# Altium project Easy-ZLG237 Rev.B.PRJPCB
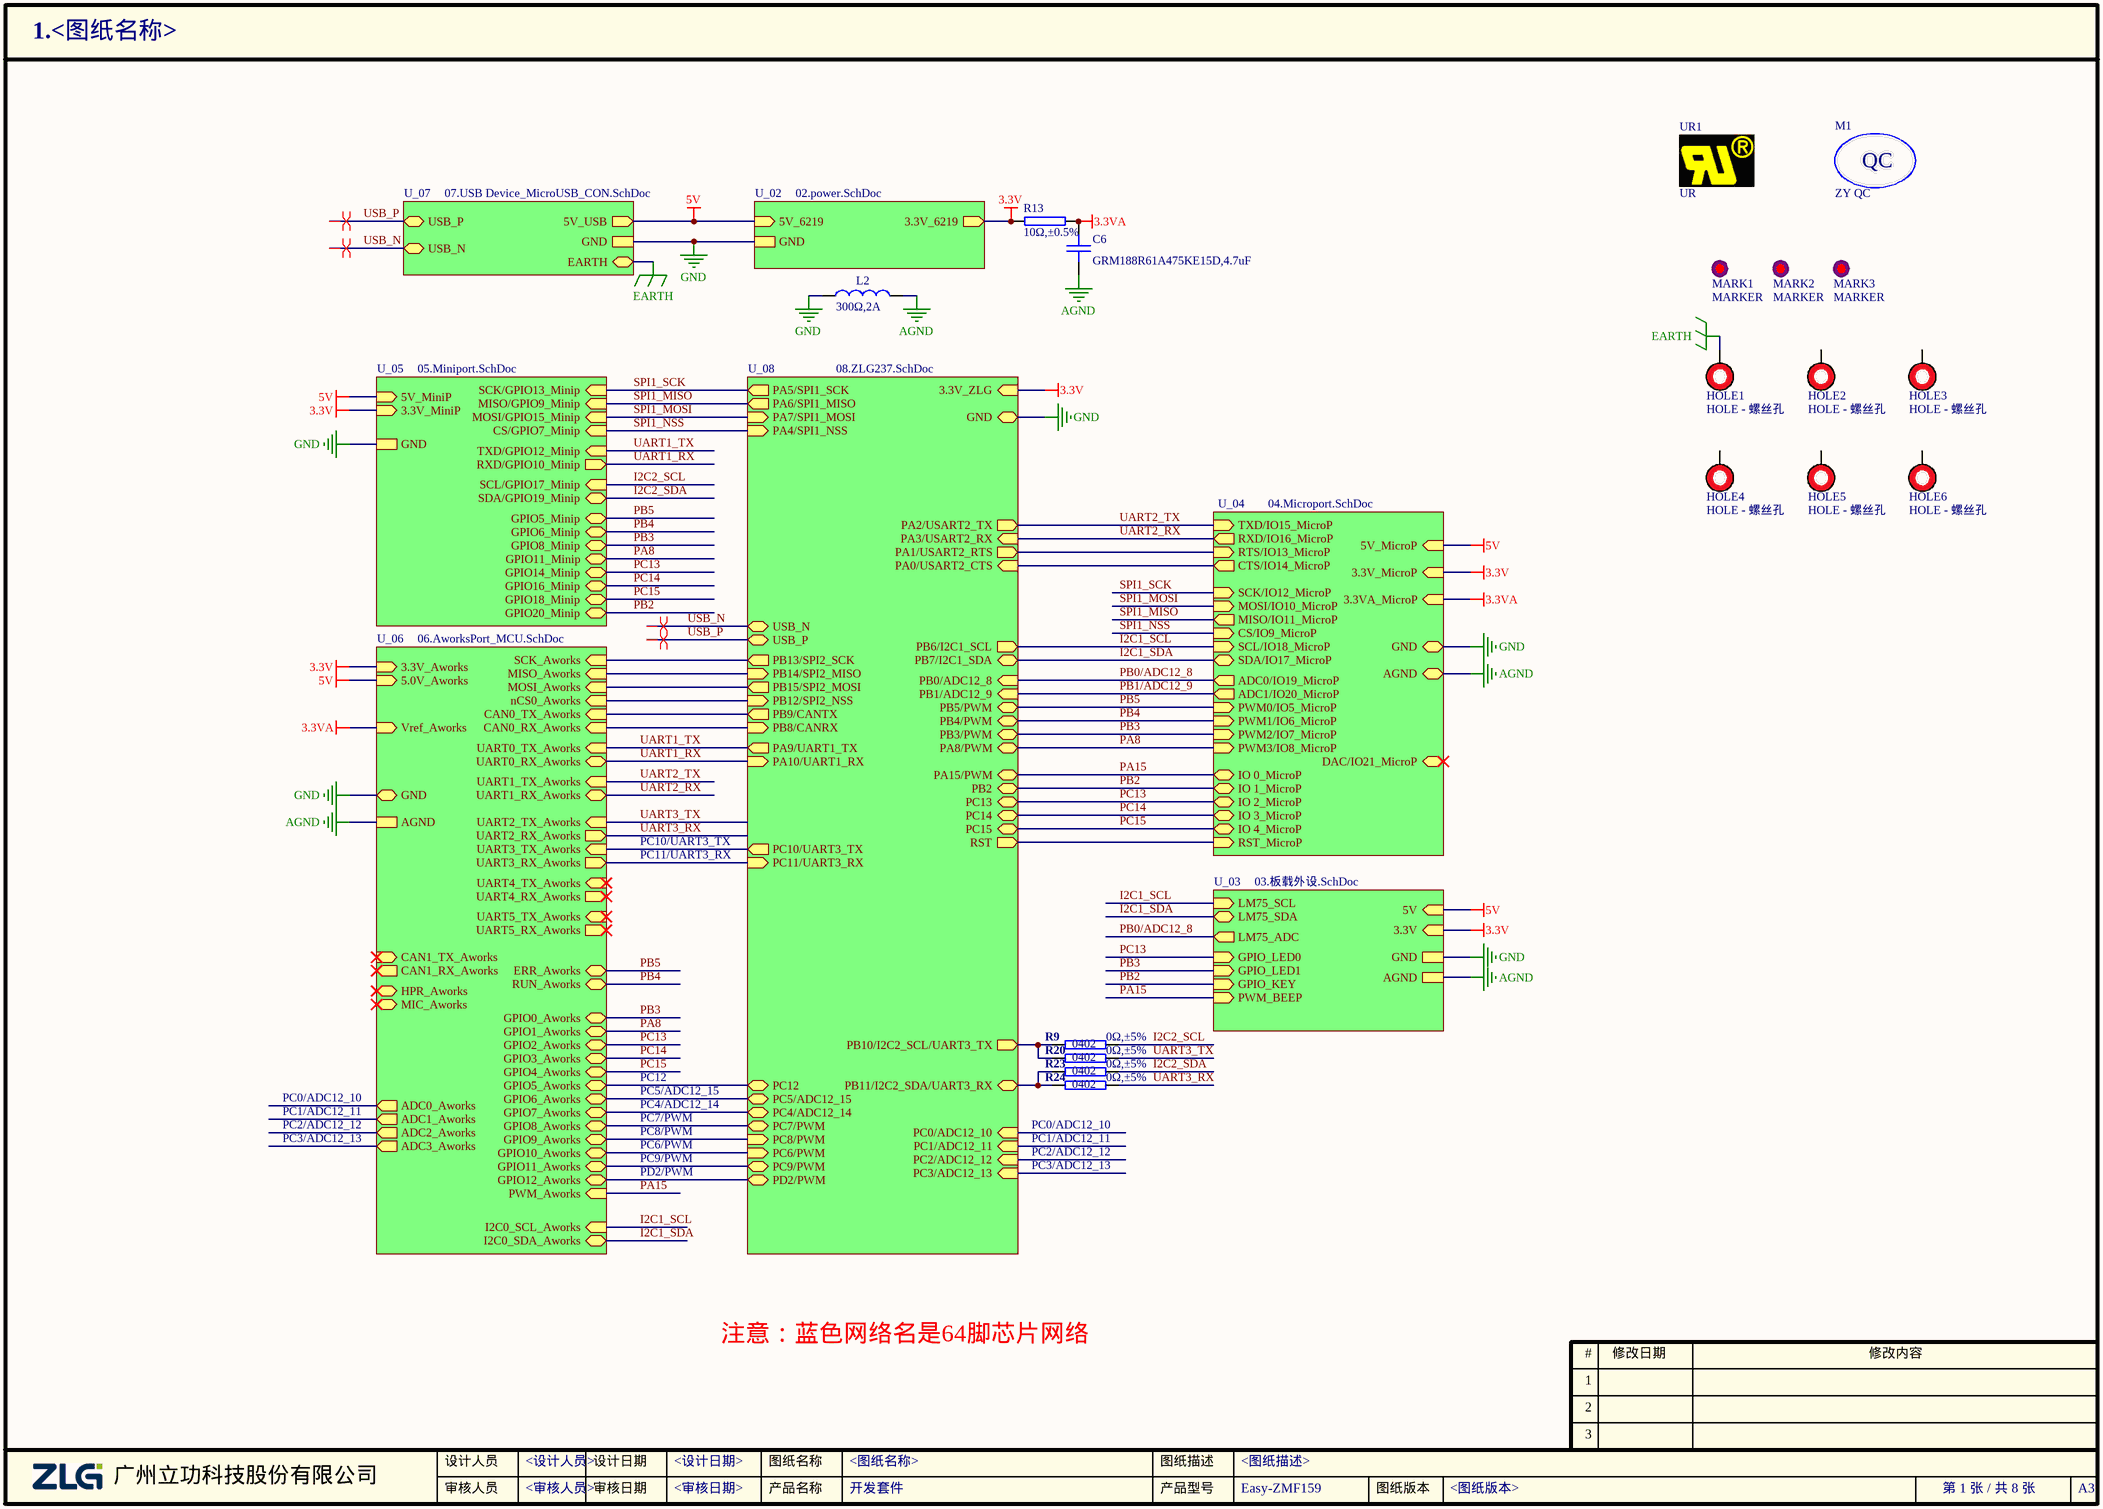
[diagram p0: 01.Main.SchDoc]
8 sheets, 111 parts. Net scope: hierarchical (ports join the sheet entries above them; power ports are global).
Board file: Easy-ZLG237 Rev.B.PcbDoc
Sheets:
  01.Main.SchDoc
    U_02 = 02.power.SchDoc
    U_03 = 03.板载外设.SchDoc
    U_06 = 06.AworksPort_MCU.SchDoc
    U_08 = 08.ZLG237.SchDoc
    U_07 = 07.USB Device_MicroUSB_CON.SchDoc
    U_04 = 04.Microport.SchDoc
    U_05 = 05.Miniport.SchDoc

## Sheet 01.Main.SchDoc
size A3; productModel: Easy-ZMF159; productName: 开发套件; CheckedBy: <审核人员>; Author: <设计人员>; CompanyName: 广州立功科技股份有限公司; DocumentNumber: 1; SheetNumber: 1; SheetTotal: 8; PageSetup: Record=PageOptions|CenterHorizontal=True|CenterVertical=True|PrintScale=1.00|XCorrection=1.00|YCorrection=1.00|PrintKind=0|BorderSize=5000000|LeftOffset=0|BottomOffset=0|Orientation=2|PaperLength=1000|PaperWidth=1000|Scale=100|PaperSource=7|PrintQuality=600|MediaType=1|DitherType=10|PaperKind=A4|PrintScaleMode=1; DesignDate: <设计日期>; CheckDate: <审核日期>; SheetName: <图纸名称>; SheetVersion: <图纸版本>; SheetDescription: <图纸描述>

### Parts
C6  GRM188R61A475KE15D,4.7uF  [0603C]
HOLE1  HOLE - 螺丝孔  [HOLE-2.2  - Screw]  (no BOM)
HOLE2  HOLE - 螺丝孔  [HOLE-2.2  - Screw]  (no BOM)
HOLE3  HOLE - 螺丝孔  [HOLE-2.2  - Screw]  (no BOM)
HOLE4  HOLE - 螺丝孔  [HOLE-2.2  - Screw]  (no BOM)
HOLE5  HOLE - 螺丝孔  [HOLE-2.2  - Screw]  (no BOM)
HOLE6  HOLE - 螺丝孔  [HOLE-2.2  - Screw]  (no BOM)
L2  300Ω,2A  [0805L]
M1  ZY QC  [ZY_QC]  (no BOM)
MARK1  MARKER  [MARKER-C-1.0M]  (no BOM)
MARK2  MARKER  [MARKER-C-1.0M]  (no BOM)
MARK3  MARKER  [MARKER-C-1.0M]  (no BOM)
R9  封装: 0402  [0402R]  (hidden comment: 0Ω,±5%)
R13  10Ω,±0.5%  [0402R]
R20  封装: 0402  [0402R]  (hidden comment: 0Ω,±5%)
R23  封装: 0402  [0402R]  (hidden comment: 0Ω,±5%)
R24  封装: 0402  [0402R]  (hidden comment: 0Ω,±5%)
UR1  UR  [ZY_UR-3X2]  (no BOM)

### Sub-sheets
U_02 = 02.power.SchDoc: GND, 3.3V_6219 (out), 5V_6219 (in)
U_03 = 03.板载外设.SchDoc: GPIO_LED0 (in), GPIO_LED1 (in), GPIO_KEY (in), LM75_ADC (out), PWM_BEEP (in), LM75_SCL (in), LM75_SDA (bidir), 3.3V (in), 5V (in), GND, AGND
U_04 = 04.Microport.SchDoc: 3.3V_MicroP (in), 5V_MicroP (in), MOSI/IO10_MicroP (in), CS/IO9_MicroP (in), SCK/IO12_MicroP (in), MISO/IO11_MicroP (out), IO 1_MicroP (bidir), IO 0_MicroP (bidir), IO 3_MicroP (bidir), IO 2_MicroP (bidir), IO 4_MicroP (bidir), PWM1/IO6_MicroP (in), PWM0/IO5_MicroP (in), PWM3/IO8_MicroP (in), PWM2/IO7_MicroP (in), SDA/IO17_MicroP (bidir), SCL/IO18_MicroP (in), ADC1/IO20_MicroP (out), ADC0/IO19_MicroP (out), DAC/IO21_MicroP (bidir), RST_MicroP (in), TXD/IO15_MicroP (in), RXD/IO16_MicroP (out), GND, RTS/IO13_MicroP (in), CTS/IO14_MicroP (out), AGND, 3.3VA_MicroP (in)
U_05 = 05.Miniport.SchDoc: GND, 3.3V_MiniP, GPIO5_Minip (bidir), GPIO6_Minip (bidir), CS/GPIO7_Minip (in), GPIO8_Minip (bidir), GPIO11_Minip (bidir), TXD/GPIO12_Minip (in), SCK/GPIO13_Minip (in), GPIO14_Minip (bidir), MOSI/GPIO15_Minip (in), GPIO16_Minip (bidir), SCL/GPIO17_Minip (in), GPIO18_Minip (bidir), MISO/GPIO9_Minip (in), RXD/GPIO10_Minip (out), 5V_MiniP, SDA/GPIO19_Minip (bidir), GPIO20_Minip (bidir)
U_06 = 06.AworksPort_MCU.SchDoc: AGND, 3.3V_Aworks (in), 5.0V_Aworks (in), GND, Vref_Aworks (in), SCK_Aworks (in), MISO_Aworks (in), RUN_Aworks (bidir), CAN1_RX_Aworks (out), CAN0_RX_Aworks (in), nCS0_Aworks (in), MOSI_Aworks (in), ERR_Aworks (bidir), UART0_TX_Aworks (in), CAN1_TX_Aworks (in), CAN0_TX_Aworks (in), UART1_TX_Aworks (in), UART2_TX_Aworks (in), UART3_TX_Aworks (in), UART4_TX_Aworks (in), UART5_TX_Aworks (in), UART0_RX_Aworks, UART1_RX_Aworks, UART2_RX_Aworks (out), UART3_RX_Aworks (out), UART4_RX_Aworks (out), UART5_RX_Aworks (out), HPR_Aworks (bidir), MIC_Aworks (bidir), ADC0_Aworks (out), ADC1_Aworks (out), ADC2_Aworks (out), ADC3_Aworks (out), I2C0_SCL_Aworks (in), I2C0_SDA_Aworks (bidir), GPIO0_Aworks (bidir), GPIO1_Aworks (bidir), GPIO2_Aworks (bidir), GPIO3_Aworks (bidir), GPIO4_Aworks (bidir), GPIO5_Aworks (bidir), GPIO6_Aworks (bidir), GPIO7_Aworks (bidir), GPIO8_Aworks (bidir), GPIO9_Aworks (bidir), GPIO10_Aworks (bidir), GPIO11_Aworks (bidir), GPIO12_Aworks (bidir), PWM_Aworks (in)
U_07 = 07.USB Device_MicroUSB_CON.SchDoc: 5V_USB (out), GND, USB_P (bidir), USB_N (bidir), EARTH
U_08 = 08.ZLG237.SchDoc: 3.3V_ZLG (in), GND, USB_N (bidir), USB_P (bidir), PC5/ADC12_15 (bidir), PC4/ADC12_14 (bidir), PB1/ADC12_9 (in), PB0/ADC12_8 (in), RST (out), PC14 (bidir), PA1/USART2_RTS (out), PA0/USART2_CTS (in), PA4/SPI1_NSS (in), PC15 (bidir), PB10/I2C2_SCL/UART3_TX (out), PB2 (bidir), PA5/SPI1_SCK (out), PB11/I2C2_SDA/UART3_RX (bidir), PC0/ADC12_10 (in), PC1/ADC12_11 (in), PC2/ADC12_12 (in), PC3/ADC12_13 (in), PA7/SPI1_MOSI (in), PA6/SPI1_MISO (out), PA2/USART2_TX (out), PC13 (bidir), PB7/I2C1_SDA (bidir), PB5/PWM (bidir), PB6/I2C1_SCL (out), PB9/CANTX (out), PB3/PWM (bidir), PB4/PWM (bidir), PB8/CANRX (in), PD2/PWM (bidir), PC12 (bidir), PA9/UART1_TX (out), PA10/UART1_RX (in), PC11/UART3_RX (in), PA8/PWM (bidir), PA15/PWM (bidir), PC10/UART3_TX (out), PC7/PWM (bidir), PC8/PWM (in), PB15/SPI2_MOSI (out), PC6/PWM (in), PB14/SPI2_MISO (in), PC9/PWM (bidir), PB13/SPI2_SCK (out), PB12/SPI2_NSS (in), PA3/USART2_RX (in)

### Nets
3.3V: R13.1 ; sheet U_02/3.3V_6219, sheet U_03/3.3V, sheet U_06/3.3V_Aworks, sheet U_08/3.3V_ZLG, sheet U_04/3.3V_MicroP, sheet U_05/3.3V_MiniP
3.3VA: C6.1 R13.2 ; sheet U_06/Vref_Aworks, sheet U_04/3.3VA_MicroP
5V: sheet U_02/5V_6219, sheet U_03/5V, sheet U_06/5.0V_Aworks, sheet U_07/5V_USB, sheet U_04/5V_MicroP, sheet U_05/5V_MiniP
AGND: C6.2 L2.2 ; sheet U_03/AGND, sheet U_06/AGND, sheet U_04/AGND
EARTH: HOLE1.1 ; sheet U_07/EARTH
GND: L2.1 ; sheet U_02/GND, sheet U_03/GND, sheet U_06/GND, sheet U_08/GND, sheet U_07/GND, sheet U_04/GND, sheet U_05/GND
CAN0_RX_Aworks: sheet U_06/CAN0_RX_Aworks, sheet U_08/PB8/CANRX
CAN0_TX_Aworks: sheet U_06/CAN0_TX_Aworks, sheet U_08/PB9/CANTX
CTS/IO14_MicroP: sheet U_08/PA0/USART2_CTS, sheet U_04/CTS/IO14_MicroP
I2C1_SCL: sheet U_03/LM75_SCL, sheet U_06/I2C0_SCL_Aworks, sheet U_08/PB6/I2C1_SCL, sheet U_04/SCL/IO18_MicroP
I2C1_SDA: sheet U_03/LM75_SDA, sheet U_06/I2C0_SDA_Aworks, sheet U_08/PB7/I2C1_SDA, sheet U_04/SDA/IO17_MicroP
I2C2_SCL: R9.2 ; sheet U_05/SCL/GPIO17_Minip
I2C2_SDA: R23.2 ; sheet U_05/SDA/GPIO19_Minip
MISO_Aworks: sheet U_06/MISO_Aworks, sheet U_08/PB14/SPI2_MISO
MOSI_Aworks: sheet U_06/MOSI_Aworks, sheet U_08/PB15/SPI2_MOSI
nCS0_Aworks: sheet U_06/nCS0_Aworks, sheet U_08/PB12/SPI2_NSS
PA1/USART2_RTS: sheet U_08/PA1/USART2_RTS, sheet U_04/RTS/IO13_MicroP
PA8: sheet U_06/GPIO1_Aworks, sheet U_08/PA8/PWM, sheet U_04/PWM3/IO8_MicroP, sheet U_05/GPIO11_Minip
PA15: sheet U_03/PWM_BEEP, sheet U_06/PWM_Aworks, sheet U_08/PA15/PWM, sheet U_04/IO 0_MicroP
PB0/ADC12_8: sheet U_03/LM75_ADC, sheet U_08/PB0/ADC12_8, sheet U_04/ADC0/IO19_MicroP
PB1/ADC12_9: sheet U_08/PB1/ADC12_9, sheet U_04/ADC1/IO20_MicroP
PB2: sheet U_03/GPIO_KEY, sheet U_08/PB2, sheet U_04/IO 1_MicroP, sheet U_05/GPIO20_Minip
PB3: sheet U_03/GPIO_LED1, sheet U_06/GPIO0_Aworks, sheet U_08/PB3/PWM, sheet U_04/PWM2/IO7_MicroP, sheet U_05/GPIO8_Minip
PB4: sheet U_06/RUN_Aworks, sheet U_08/PB4/PWM, sheet U_04/PWM1/IO6_MicroP, sheet U_05/GPIO6_Minip
PB5: sheet U_06/ERR_Aworks, sheet U_08/PB5/PWM, sheet U_04/PWM0/IO5_MicroP, sheet U_05/GPIO5_Minip
PB10/I2C2_SCL/UART3_TX: R9.1 R20.1 ; sheet U_08/PB10/I2C2_SCL/UART3_TX
PB11/I2C2_SDA/UART3_RX: R23.1 R24.1 ; sheet U_08/PB11/I2C2_SDA/UART3_RX
PB13/SPI2_SCK: sheet U_06/SCK_Aworks, sheet U_08/PB13/SPI2_SCK
PC0/ADC12_10: sheet U_06/ADC0_Aworks, sheet U_08/PC0/ADC12_10
PC1/ADC12_11: sheet U_06/ADC1_Aworks, sheet U_08/PC1/ADC12_11
PC2/ADC12_12: sheet U_06/ADC2_Aworks, sheet U_08/PC2/ADC12_12
PC3/ADC12_13: sheet U_06/ADC3_Aworks, sheet U_08/PC3/ADC12_13
PC4/ADC12_14: sheet U_06/GPIO7_Aworks, sheet U_08/PC4/ADC12_14
PC5/ADC12_15: sheet U_06/GPIO6_Aworks, sheet U_08/PC5/ADC12_15
PC6/PWM: sheet U_06/GPIO10_Aworks, sheet U_08/PC6/PWM
PC7/PWM: sheet U_06/GPIO8_Aworks, sheet U_08/PC7/PWM
PC8/PWM: sheet U_06/GPIO9_Aworks, sheet U_08/PC8/PWM
PC9/PWM: sheet U_06/GPIO11_Aworks, sheet U_08/PC9/PWM
PC10/UART3_TX: sheet U_06/UART3_TX_Aworks, sheet U_08/PC10/UART3_TX
PC11/UART3_RX: sheet U_06/UART3_RX_Aworks, sheet U_08/PC11/UART3_RX
PC12: sheet U_06/GPIO5_Aworks, sheet U_08/PC12
PC13: sheet U_03/GPIO_LED0, sheet U_06/GPIO2_Aworks, sheet U_08/PC13, sheet U_04/IO 2_MicroP, sheet U_05/GPIO14_Minip
PC14: sheet U_06/GPIO3_Aworks, sheet U_08/PC14, sheet U_04/IO 3_MicroP, sheet U_05/GPIO16_Minip
PC15: sheet U_06/GPIO4_Aworks, sheet U_08/PC15, sheet U_04/IO 4_MicroP, sheet U_05/GPIO18_Minip
PD2/PWM: sheet U_06/GPIO12_Aworks, sheet U_08/PD2/PWM
RST: sheet U_08/RST, sheet U_04/RST_MicroP
SPI1_MISO: sheet U_08/PA6/SPI1_MISO, sheet U_04/MISO/IO11_MicroP, sheet U_05/MISO/GPIO9_Minip
SPI1_MOSI: sheet U_08/PA7/SPI1_MOSI, sheet U_04/MOSI/IO10_MicroP, sheet U_05/MOSI/GPIO15_Minip
SPI1_NSS: sheet U_08/PA4/SPI1_NSS, sheet U_04/CS/IO9_MicroP, sheet U_05/CS/GPIO7_Minip
SPI1_SCK: sheet U_08/PA5/SPI1_SCK, sheet U_04/SCK/IO12_MicroP, sheet U_05/SCK/GPIO13_Minip
UART1_RX: sheet U_06/UART0_RX_Aworks, sheet U_08/PA10/UART1_RX, sheet U_05/RXD/GPIO10_Minip
UART1_TX: sheet U_06/UART0_TX_Aworks, sheet U_08/PA9/UART1_TX, sheet U_05/TXD/GPIO12_Minip
UART2_RX: sheet U_06/UART1_RX_Aworks, sheet U_08/PA3/USART2_RX, sheet U_04/RXD/IO16_MicroP
UART2_TX: sheet U_06/UART1_TX_Aworks, sheet U_08/PA2/USART2_TX, sheet U_04/TXD/IO15_MicroP
UART3_RX: R24.2 ; sheet U_06/UART2_RX_Aworks
UART3_TX: R20.2 ; sheet U_06/UART2_TX_Aworks
USB_N: sheet U_08/USB_N, sheet U_07/USB_N
USB_P: sheet U_08/USB_P, sheet U_07/USB_P

Not connected (* = marked no-connect by the designer): HOLE2 1; HOLE3 1; HOLE4 1; HOLE5 1; HOLE6 1; MARK1 0; MARK2 0; MARK3 0

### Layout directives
differential pair: USB_N, USB_P

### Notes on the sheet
- 注意：蓝色网络名是64脚芯片网络

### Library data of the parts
C6 = 1.02.01.0080: GRM188R61A475KE15D,4.7uF,±10%,10V,X5R,0603,muRata,RoHS; 名称: 电容; 封装: 0603; 贴片和直插: SMT; PCB备注: 160602yjh; 器件优选方案: 正常状态，可以选用
L2 = 1.03.03.0010: 300Ω,2A,DCR80mΩ,BH05Y354S-300R,SMD,0805,丰晶,RoHS; 名称: 磁珠; 封装: 0805; 贴片和直插: SMT; 器件优选方案: 正常状态，可以选用
R9 R20 R23 R24 = 1.01.17.0004: 0Ω,±5%,0402,RALEC,RoHS; 名称: 电阻; 设备封装名称: R0402_0R; 贴片和直插: SMT; 器件优选方案: 正常状态，可以选用
R13 = 1.01.17.0049: 10Ω,±0.5%,0402,RoHS; 名称: 电阻; 封装: 0402; 设备封装名称: R0402_10R_0.5%; 厂商: Ralec; 贴片和直插: SMT; 器件优选方案: 正常状态，可以选用

## Sheet 02.power.SchDoc
size A4; productmodel: Easy-ZMF159; productName: 开发套件; CheckedBy: <审核日期>; Author: <设计人员>; CompanyName: 广州立功科技股份有限; DocumentNumber: 2; SheetNumber: 2; SheetTotal: 8; PageSetup: Record=PageOptions|CenterHorizontal=True|CenterVertical=True|PrintScale=1.00|XCorrection=1.00|YCorrection=1.00|PrintKind=0|BorderSize=5000000|LeftOffset=0|BottomOffset=0|Orientation=2|PaperLength=1000|PaperWidth=1000|Scale=100|PaperSource=7|PrintQuality=600|MediaType=1|DitherType=10|PaperKind=A4|PrintScaleMode=1; DesignDate: <设计日期>; CheckDate: <审核人员>; SheetName: <图纸名称>; SheetVersion: <图纸版本>; SheetDescription: <图纸描述>
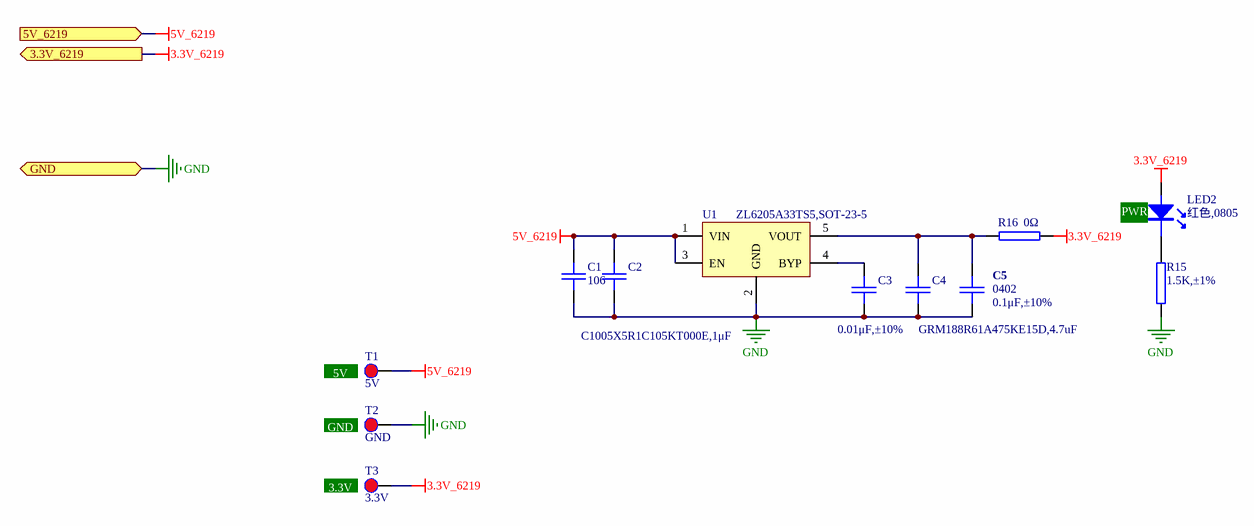
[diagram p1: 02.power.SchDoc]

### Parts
C1  106  [0805C]
C2  C1005X5R1C105KT000E,1μF  [0402C]
C3  0.01μF,±10%  [0402C]
C4  GRM188R61A475KE15D,4.7uF  [0603C]
C5  封装: 0402  [0402C]  (hidden comment: 0.1μF,±10%)
LED2  value 红色,0805  [LED-0805]  (hidden comment: LED1)
R15  1.5K,±1%  [0402R]
R16  0Ω  [0603R]
T1  5V  [PAD-40]  (no BOM)
T2  GND  [PAD-40]  (no BOM)
T3  3.3V  [PAD-40]  (no BOM)
U1  ZL6205A33TS5,SOT-23-5  [SOT-23-5]

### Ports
3.3V_6219 (out), 5V_6219 (in), GND

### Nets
3.3V_6219: LED2.1 R16.2 T3.1 ; port 3.3V_6219  [project net 3.3V]
5V_6219: C1.1 C2.1 T1.1 U1.1(VIN) U1.3(EN) ; port 5V_6219  [project net 5V]
GND: C1.2 C2.2 C3.2 C4.2 C5.2 R15.1 T2.1 U1.2(GND) ; port GND
NetC3_1: C3.1 U1.4(BYP)
NetC4_1: C4.1 C5.1 R16.1 U1.5(VOUT)
NetLED2_2: LED2.2 R15.2

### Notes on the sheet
- (near LED2) PWR
- (near T1) 5V
- (near T2) GND
- (near T3) 3.3V

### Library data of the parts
C1 = 1.02.02.0055: 106,10μF,±10%,10V,X5R,0805,RoHS; 名称: 电容; 封装: 0805; 贴片和直插: SMT; 器件优选方案: 量产物料,优先选用; 设备封装名称: C0805_106_X5R_10V_10%
C2 = 1.02.17.0092: C1005X5R1C105KT000E,1μF,±10%,16V,X5R,0402,TDK,RoHS; 名称: 电容; 封装: 0402; 贴片和直插: SMT; PCB备注: 无数据手册，依据采购部提供的信息添加的封装。; 器件优选方案: 正常状态，可以选用
C3 = 1.02.17.0019: GRM155R71H103KA88D,0.01μF,±10%,50V,X7R,0402,muRata,RoHS; 名称: 电容; 封装: 0402; 设备封装名称: C0402_0.01uF_X7R_50V_10%; 贴片和直插: SMT; 器件优选方案: 正常状态，可以选用
C4 = 1.02.01.0080: as C6 on sheet 01.Main
C5 = 1.02.17.0006: 0.1μF,±10%,16V,X7R,0402,RoHS; 名称: 电容; 设备封装名称: C0402_0.1uF_X7R_16V_10%; 贴片和直插: SMT
LED2 = 1.04.05.0001: 红色,0805,0805,RoHS; 名称: 发光二极管; 封装: 0805; 设备封装名称: LED0805-RED; 贴片和直插: SMT; 器件优选方案: 样品物料,谨慎选用
R15 = 1.01.17.0011: 1.5K,±1%,0402,RALEC,RoHS; 名称: 电阻; 封装: 0402; 设备封装名称: R0402_1.5K_1%; 贴片和直插: SMT; 器件优选方案: 正常状态，可以选用
R16 = 1.01.01.0001: 名称: 电阻; 封装: 0603; 设备封装名称: R0603_0R; 厂商: Ralec; 贴片和直插: SMT; 器件优选方案: 状态正常
T1-T3 = TEST-DOT
U1 = 08.09.03069: ZL6205A33TS5,SOT-23-5,ZLG; 名称: 集成电路; 贴片和直插: SMT; PCB备注: 190806hcj; 器件优选方案: 待导入物料

## Sheet 03.板载外设.SchDoc
size A4; productModel: Easy-ZMF159; productName: 开发套件; CheckedBy: <审核日期>; Author: <设计人员>; CompanyName: 广州立功科技股份有限; DocumentNumber: 3; SheetNumber: 3; SheetTotal: 8; PageSetup: Record=PageOptions|CenterHorizontal=True|CenterVertical=True|PrintScale=1.00|XCorrection=1.00|YCorrection=1.00|PrintKind=0|BorderSize=5000000|LeftOffset=0|BottomOffset=0|Orientation=2|PaperLength=1000|PaperWidth=1000|Scale=100|PaperSource=7|PrintQuality=600|MediaType=1|DitherType=10|PaperKind=A4|PrintScaleMode=1; DesignDate: <设计日期>; CheckDate: <审核人员>; SheetName: <图纸名称>; SheetVersion: <图纸版本>; SheetDescription: <图纸描述>
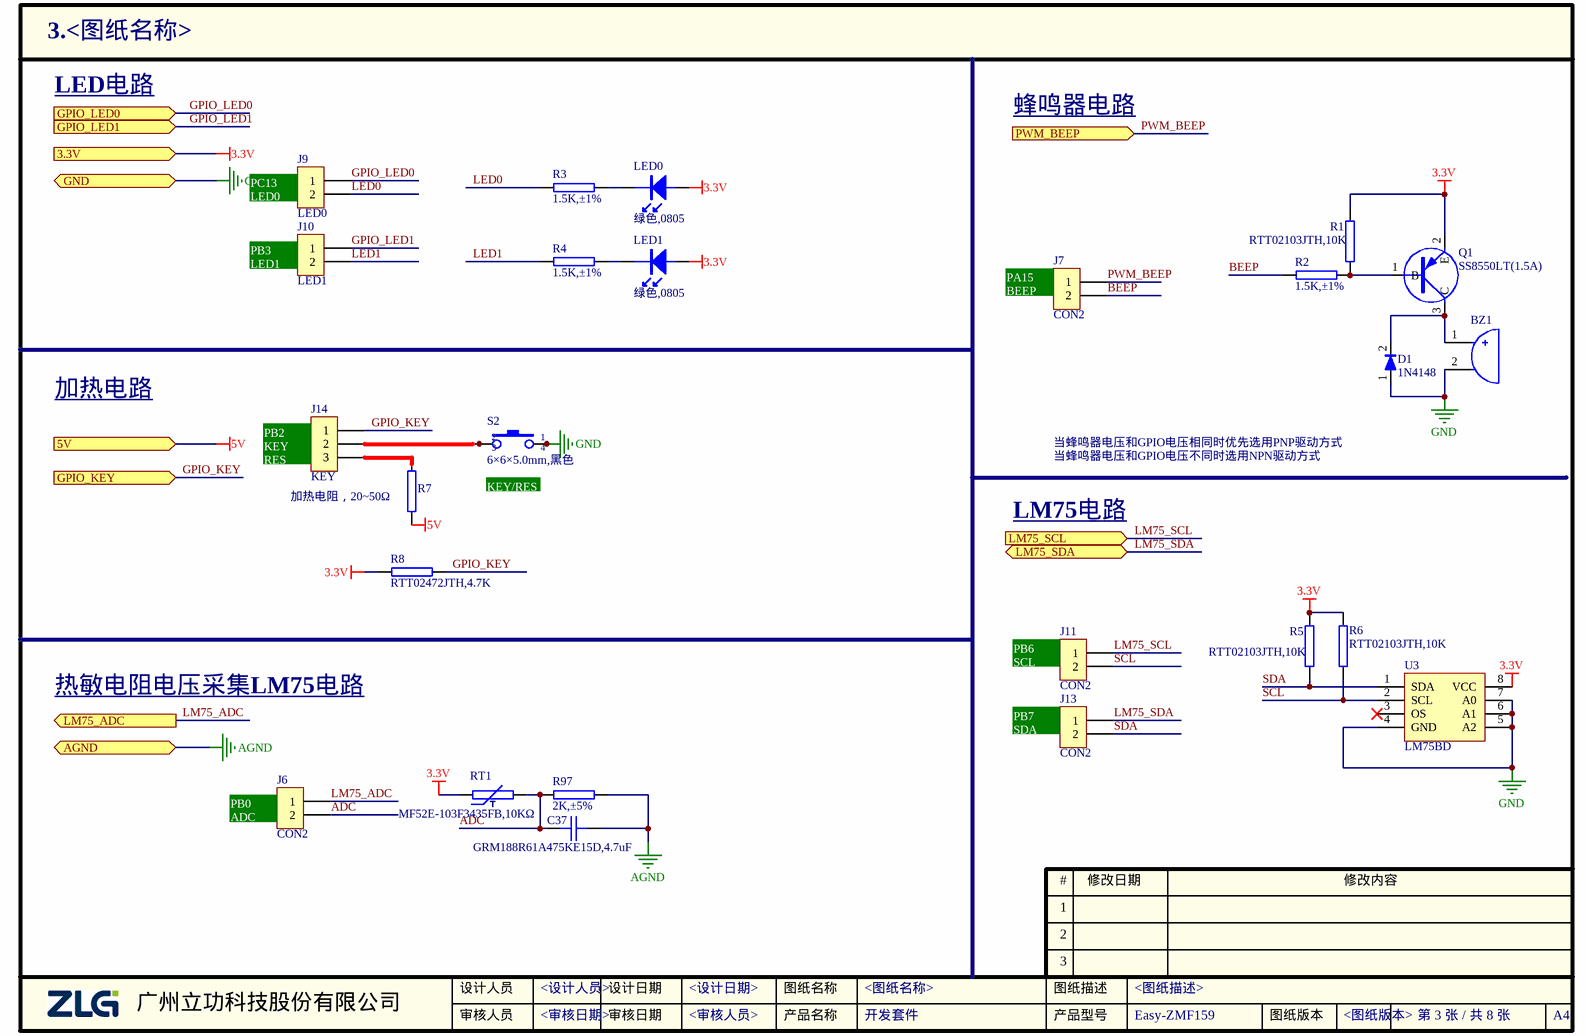
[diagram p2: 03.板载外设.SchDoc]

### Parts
BZ1  BUZZER2  [BUZZ-4/9]  (value not drawn)
C37  GRM188R61A475KE15D,4.7uF  [0603C]
D1  value 1N4148  [SOD-323]  (hidden comment: DIODE1)
J6  CON2  [SIP-2-2.54]
J7  CON2  [SIP-2-2.54]
J9  LED0  [SIP-2-2.54]
J10  LED1  [SIP-2-2.54]
J11  CON2  [SIP-2-2.54]
J13  CON2  [SIP-2-2.54]
J14  KEY  [SIP-3-2.54]
LED0  value 绿色,0805  [LED-0805]  (hidden comment: LED0)
LED1  value 绿色,0805  [LED-0805]  (hidden comment: LED1)
Q1  value SS8550LT(1.5A)  [SOT-23]  (hidden comment: PNP-1)
R1  RTT02103JTH,10K  [0402R]
R2  1.5K,±1%  [0402R]
R3  1.5K,±1%  [0402R]
R4  1.5K,±1%  [0402R]
R5  RTT02103JTH,10K  [0402R]
R6  RTT02103JTH,10K  [0402R]
R7  20Ω,±5%  [RESAD1778W80L1450D430P]  (value not drawn)
R8  RTT02472JTH,4.7K  [0402R]
R97  2K,±5%  [0402R]
RT1  MF52E-103F3435FB,10KΩ  [MF52E-103F3435FB]
S2  value 6×6×5.0mm,黑色  [KEY-6S]  (hidden comment: KEY/RES)
U3  value LM75BD  [SOIC127P600X175-8N]  (hidden comment: LM75B)

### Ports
3.3V (in), 5V (in), AGND, GND, GPIO_KEY (in), GPIO_LED0 (in), GPIO_LED1 (in), LM75_ADC (out), LM75_SCL (in), LM75_SDA (bidir), PWM_BEEP (in)

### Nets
3.3V: LED0.1 LED1.1 Q1.2(E) R1.2 R5.2 R6.2 R8.1 RT1.1 U3.8(VCC) ; port 3.3V
5V: R7.1 ; port 5V
AGND: C37.2 R97.2 ; port AGND
GND: BZ1.2(B) D1.1 S2.1 S2.4 U3.4(GND) U3.5(A2) U3.6(A1) U3.7(A0) ; port GND
ADC: C37.1 J6.2 R97.1 RT1.2  [project net ADC_3]
BEEP: J7.2 R2.2  [project net BEEP_3]
GPIO_KEY: J14.1 R8.2 ; port GPIO_KEY  [project net PB2]
GPIO_LED0: J9.1 ; port GPIO_LED0  [project net PC13]
GPIO_LED1: J10.1 ; port GPIO_LED1  [project net PB3]
LED0: J9.2 R3.2  [project net LED0_3]
LED1: J10.2 R4.2  [project net LED1_3]
LM75_ADC: J6.1 ; port LM75_ADC  [project net PB0/ADC12_8]
LM75_SCL: J11.1 ; port LM75_SCL  [project net I2C1_SCL]
LM75_SDA: J13.1 ; port LM75_SDA  [project net I2C1_SDA]
PWM_BEEP: J7.1 ; port PWM_BEEP  [project net PA15]
SCL: J11.2 R6.1 U3.2(SCL)  [project net SCL_3]
SDA: J13.2 R5.1 U3.1(SDA)  [project net SDA_3]
NetBZ1_1: BZ1.1(A) D1.2 Q1.3(C)
NetJ14_2: J14.2 S2.2 S2.3
NetJ14_3: J14.3 R7.2
NetLED0_2: LED0.2 R3.1
NetLED1_2: LED1.2 R4.1
NetQ1_1: Q1.1(B) R1.1 R2.1

Not connected (* = marked no-connect by the designer): U3 3(OS)*

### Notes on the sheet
- LED电路
- 蜂鸣器电路
- (near J9) PC13
  LED0
- (near J10) PB3
  LED1
- (near J7) PA15
  BEEP
- 加热电路
- 当蜂鸣器电压和GPIO电压相同时优先选用PNP驱动方式
- (near J14) PB2
  KEY
  RES
- 加热电阻，20~50Ω
- (near S2) KEY/RES
- LM75电路
- 当蜂鸣器电压和GPIO电压不同时选用NPN驱动方式
- 热敏电阻电压采集LM75电路
- (near J11) PB6
  SCL
- (near J13) PB7
  SDA
- (near J6) PB0
  ADC

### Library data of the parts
BZ1 = 1.06.09.0016: Buzzer有极性; Value: AS-905I-LF,无源; 名称: 讯响器; 厂商: 常州笠翔; 型号: AS-905I-LF,无源,Ф9×4.8mm; 贴片和直插: THT; PCB备注: Flq-Shcj-Twrj-150113; 器件优选方案: 量产物料,优先选用
C37 = 1.02.01.0080: as C6 on sheet 01.Main
D1 = 1.04.07.0027: 1N4148,SOD-323,RoHS; 名称: 二极管; 设备封装名称: SOD-323_1N4148; 贴片和直插: SMT
J6 J7 J11 J13 = CON2: Connector
J9 J10 = CON2: Connector; 物料代码: 1.10.03.0164
J14 = CON3: Connector; 物料代码: 1.10.03.0164
LED0 LED1 = 1.04.05.0002: 绿色,0805,0805,RoHS; 名称: 发光二极管; 封装: 0805; 设备封装名称: LED0805-GREEN; 贴片和直插: SMT; 器件优选方案: 样品物料,谨慎选用
Q1 = 1.04.09.0002: PNP Transistor; 名称: 三极管; 设备封装名称: SOT-23_SS8550LT; 厂商: 江苏长电; 贴片和直插: SMT
R1 R5 R6 = 1.01.17.0006: RTT02103JTH,10K,±5%,0402,RALEC,RoHS; 名称: 电阻; 封装: 0402; 设备封装名称: R0402_10K; 贴片和直插: SMT; 器件优选方案: 正常状态，可以选用
R2-R4 = 1.01.17.0011: as R15 on sheet 02.power
R7 = 1.01.10.0003: 20Ω,±5%,2W,Ф5.5×16mm,RoHS; 名称: 电阻; 贴片和直插: THT
R8 = 1.01.17.0019: RTT02472JTH,4.7K,±5%,0402,RALEC,RoHS; 名称: 电阻; 封装: 0402; 设备封装名称: R0402_4.7K; 贴片和直插: SMT; 器件优选方案: 正常状态，可以选用
R97 = 1.01.17.0032: 2K,±5%,0402,RALEC,RoHS; 名称: 电阻; 封装: 0402; 设备封装名称: R0402_2K; 贴片和直插: SMT; 器件优选方案: 正常状态，可以选用
RT1 = 1.01.14.0023: MF52E-103F3435FB,10KΩ,THT,安培龙; 名称: 热敏电阻; PCB备注: 180523ZW; 器件优选方案: 正常状态，可以选用
S2 = 1.09.01.0003: 6×6×5.0mm,黑色,SMD,,*; 名称: 轻触按键; 贴片和直插: SMT
U3 = 1.05.10.0602: LM75BD,SO-9,NXP,RoHS; 名称: IC; 封装: SO-8; 贴片和直插: SMT; 器件优选方案: 样品物料,谨慎选用

## Sheet 06.AworksPort_MCU.SchDoc
size A4; productModel: Easy-ZMF159; productName: 开发套件; CheckedBy: <审核日期>; Author: <设计人员>; CompanyName: 广州立功科技股份有限; DocumentNumber: 6; SheetNumber: 6; SheetTotal: 8; PageSetup: Record=PageOptions|CenterHorizontal=True|CenterVertical=True|PrintScale=1.00|XCorrection=1.00|YCorrection=1.00|PrintKind=0|BorderSize=5000000|LeftOffset=0|BottomOffset=0|Orientation=2|PaperLength=1000|PaperWidth=1000|Scale=100|PaperSource=7|PrintQuality=600|MediaType=1|DitherType=10|PaperKind=A4|PrintScaleMode=1; DesignDate: <设计日期>; CheckDate: <审核人员>; SheetName: <图纸名称>; SheetVersion: <图纸版本>; SheetDescription: <图纸描述>
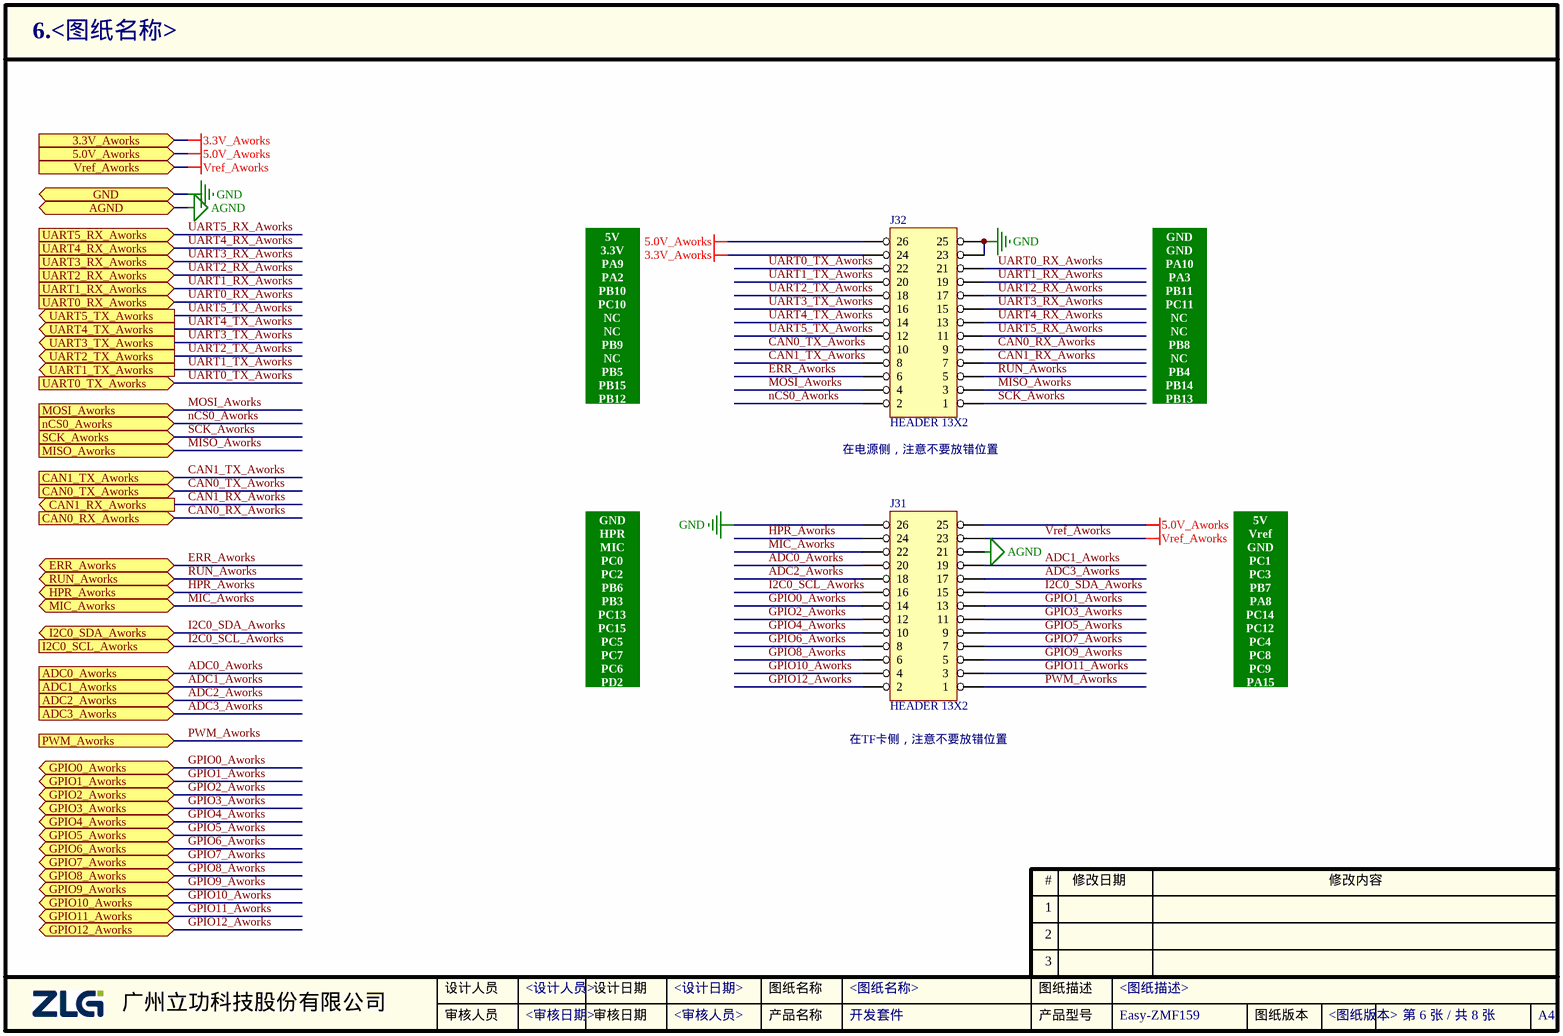
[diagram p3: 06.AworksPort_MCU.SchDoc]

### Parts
J31  HEADER 13X2  [IDC-26]
J32  HEADER 13X2  [IDC-26]

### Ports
3.3V_Aworks (in), 5.0V_Aworks (in), ADC0_Aworks (in), ADC1_Aworks (in), ADC2_Aworks (in), ADC3_Aworks (in), AGND, CAN0_RX_Aworks (in), CAN0_TX_Aworks (in), CAN1_RX_Aworks (out), CAN1_TX_Aworks (in), ERR_Aworks (bidir), GND, GPIO0_Aworks (bidir), GPIO1_Aworks (bidir), GPIO2_Aworks (bidir), GPIO3_Aworks (bidir), GPIO4_Aworks (bidir), GPIO5_Aworks (bidir), GPIO6_Aworks (bidir), GPIO7_Aworks (bidir), GPIO8_Aworks (bidir), GPIO9_Aworks (bidir), GPIO10_Aworks (bidir), GPIO11_Aworks (bidir), GPIO12_Aworks (bidir), HPR_Aworks (bidir), I2C0_SCL_Aworks (in), I2C0_SDA_Aworks (bidir), MIC_Aworks (bidir), MISO_Aworks (in), MOSI_Aworks (in), nCS0_Aworks (in), PWM_Aworks (in), RUN_Aworks (bidir), SCK_Aworks (in), UART0_RX_Aworks (in), UART0_TX_Aworks (in), UART1_RX_Aworks (in), UART1_TX_Aworks (out), UART2_RX_Aworks (in), UART2_TX_Aworks (out), UART3_RX_Aworks (in), UART3_TX_Aworks (out), UART4_RX_Aworks (in), UART4_TX_Aworks (out), UART5_RX_Aworks (in), UART5_TX_Aworks (out), Vref_Aworks (in)

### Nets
3.3V_Aworks: J32.24 ; port 3.3V_Aworks  [project net 3.3V]
5.0V_Aworks: J31.25 J32.26 ; port 5.0V_Aworks  [project net 5V]
AGND: J31.21 ; port AGND
GND: J31.26 J32.23 J32.25 ; port GND
Vref_Aworks: J31.23 ; port Vref_Aworks  [project net 3.3VA]
ADC0_Aworks: J31.20 ; port ADC0_Aworks  [project net PC0/ADC12_10]
ADC1_Aworks: J31.19 ; port ADC1_Aworks  [project net PC1/ADC12_11]
ADC2_Aworks: J31.18 ; port ADC2_Aworks  [project net PC2/ADC12_12]
ADC3_Aworks: J31.17 ; port ADC3_Aworks  [project net PC3/ADC12_13]
CAN0_RX_Aworks: J32.9 ; port CAN0_RX_Aworks
CAN0_TX_Aworks: J32.10 ; port CAN0_TX_Aworks
CAN1_RX_Aworks: J32.7 ; port CAN1_RX_Aworks
CAN1_TX_Aworks: J32.8 ; port CAN1_TX_Aworks
ERR_Aworks: J32.6 ; port ERR_Aworks  [project net PB5]
GPIO0_Aworks: J31.14 ; port GPIO0_Aworks  [project net PB3]
GPIO1_Aworks: J31.13 ; port GPIO1_Aworks  [project net PA8]
GPIO2_Aworks: J31.12 ; port GPIO2_Aworks  [project net PC13]
GPIO3_Aworks: J31.11 ; port GPIO3_Aworks  [project net PC14]
GPIO4_Aworks: J31.10 ; port GPIO4_Aworks  [project net PC15]
GPIO5_Aworks: J31.9 ; port GPIO5_Aworks  [project net PC12]
GPIO6_Aworks: J31.8 ; port GPIO6_Aworks  [project net PC5/ADC12_15]
GPIO7_Aworks: J31.7 ; port GPIO7_Aworks  [project net PC4/ADC12_14]
GPIO8_Aworks: J31.6 ; port GPIO8_Aworks  [project net PC7/PWM]
GPIO9_Aworks: J31.5 ; port GPIO9_Aworks  [project net PC8/PWM]
GPIO10_Aworks: J31.4 ; port GPIO10_Aworks  [project net PC6/PWM]
GPIO11_Aworks: J31.3 ; port GPIO11_Aworks  [project net PC9/PWM]
GPIO12_Aworks: J31.2 ; port GPIO12_Aworks  [project net PD2/PWM]
HPR_Aworks: J31.24 ; port HPR_Aworks
I2C0_SCL_Aworks: J31.16 ; port I2C0_SCL_Aworks  [project net I2C1_SCL]
I2C0_SDA_Aworks: J31.15 ; port I2C0_SDA_Aworks  [project net I2C1_SDA]
MIC_Aworks: J31.22 ; port MIC_Aworks
MISO_Aworks: J32.3 ; port MISO_Aworks
MOSI_Aworks: J32.4 ; port MOSI_Aworks
nCS0_Aworks: J32.2 ; port nCS0_Aworks
PWM_Aworks: J31.1 ; port PWM_Aworks  [project net PA15]
RUN_Aworks: J32.5 ; port RUN_Aworks  [project net PB4]
SCK_Aworks: J32.1 ; port SCK_Aworks  [project net PB13/SPI2_SCK]
UART0_RX_Aworks: J32.21 ; port UART0_RX_Aworks  [project net UART1_RX]
UART0_TX_Aworks: J32.22 ; port UART0_TX_Aworks  [project net UART1_TX]
UART1_RX_Aworks: J32.19 ; port UART1_RX_Aworks  [project net UART2_RX]
UART1_TX_Aworks: J32.20 ; port UART1_TX_Aworks  [project net UART2_TX]
UART2_RX_Aworks: J32.17 ; port UART2_RX_Aworks  [project net UART3_RX]
UART2_TX_Aworks: J32.18 ; port UART2_TX_Aworks  [project net UART3_TX]
UART3_RX_Aworks: J32.15 ; port UART3_RX_Aworks  [project net PC11/UART3_RX]
UART3_TX_Aworks: J32.16 ; port UART3_TX_Aworks  [project net PC10/UART3_TX]
UART4_RX_Aworks: J32.13 ; port UART4_RX_Aworks
UART4_TX_Aworks: J32.14 ; port UART4_TX_Aworks
UART5_RX_Aworks: J32.11 ; port UART5_RX_Aworks
UART5_TX_Aworks: J32.12 ; port UART5_TX_Aworks

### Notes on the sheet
- 3.3V
- 5V
- GND
- PC10
- PB10
- PA2
- PA9
- PC11
- PB11
- PA3
- PA10
- PB15
- PB5
- NC
- PB9
- PB4
- PB8
- PB14
- PB12
- PB13
- (near J32) 在电源侧，注意不要放错位置
- PC0
- PC2
- MIC
- HPR
- PC3
- PC1
- Vref
- PB6
- PC5
- PC7
- PC15
- PC13
- PB3
- PB7
- PC4
- PC8
- PC12
- PC14
- PA8
- PD2
- PC6
- PC9
- PA15
- (near J31) 在TF卡侧，注意不要放错位置

## Sheet 08.ZLG237.SchDoc
size A3; productModel: Easy-ZLG237; productName: 开发套件; CheckedBy: <审核人员>; Author: <设计人员>; CompanyName: 广州立功科技股份有限公司; DocumentNumber: 8; SheetNumber: 8; SheetTotal: 8; PageSetup: Record=PageOptions|CenterHorizontal=True|CenterVertical=True|PrintScale=1.00|XCorrection=1.00|YCorrection=1.00|PrintKind=0|BorderSize=5000000|LeftOffset=0|BottomOffset=0|Orientation=2|PaperLength=1000|PaperWidth=1000|Scale=100|PaperSource=7|PrintQuality=600|MediaType=1|DitherType=10|PaperKind=A4|PrintScaleMode=1; DesignDate: <设计日期>; CheckDate: <审核日期>; SheetName: <图纸名称>; SheetVersion: <图纸版本>; SheetDescription: <图纸描述>
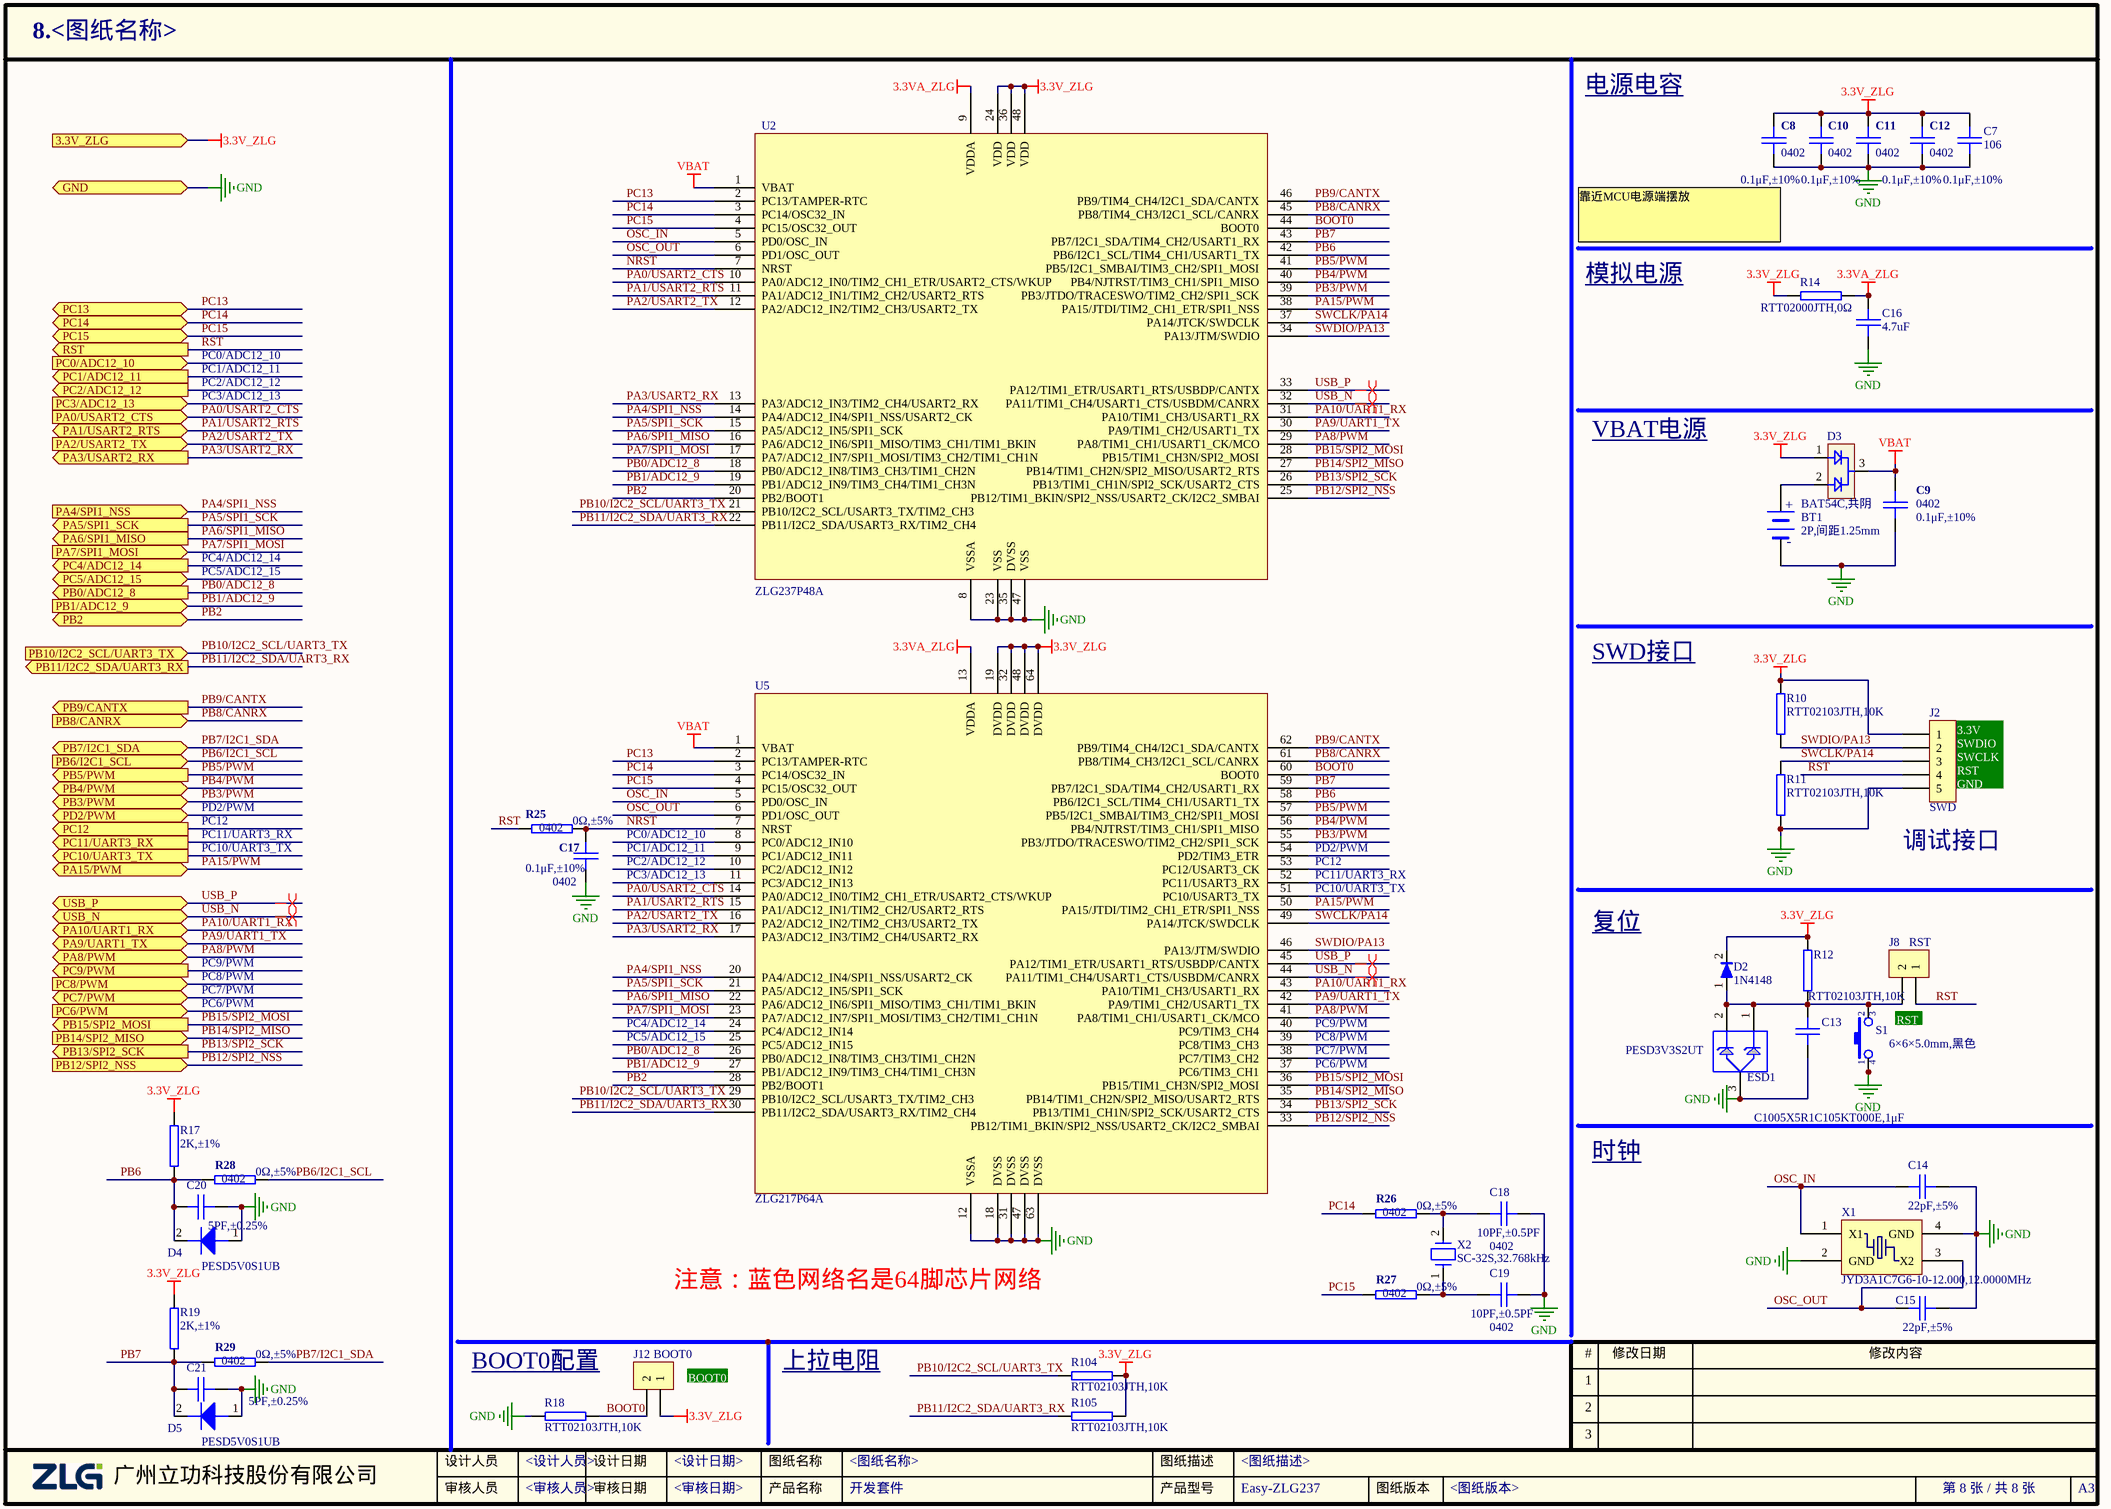
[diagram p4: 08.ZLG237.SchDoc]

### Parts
BT1  2P,间距1.25mm  [FPC2-49T]
C7  106  [0805C]
C8  封装: 0402  [0402C]  (hidden comment: 0.1μF,±10%)
C9  封装: 0402  [0402C]  (hidden comment: 0.1μF,±10%)
C10  封装: 0402  [0402C]  (hidden comment: 0.1μF,±10%)
C11  封装: 0402  [0402C]  (hidden comment: 0.1μF,±10%)
C12  封装: 0402  [0402C]  (hidden comment: 0.1μF,±10%)
C13  C1005X5R1C105KT000E,1μF  [0402C]
C14  22pF,±5%  [0402C]
C15  22pF,±5%  [0402C]
C16  4.7uF  [0603C]
C17  封装: 0402  [0402C]  (hidden comment: 0.1μF,±10%)
C18  封装: 0402  [0402C]  (hidden comment: 10PF,±0.5PF)
C19  封装: 0402  [0402C]  (hidden comment: 10PF,±0.5PF)
C20  5PF,±0.25%  [0402C]
C21  5PF,±0.25%  [0402C]
D2  value 1N4148  [SOD-323]  (hidden comment: DIODE1)
D3  BAT54C,共阴  [SOT-23]
D4  PESD5V0S1UB  [SOD-523]
D5  PESD5V0S1UB  [SOD-523]
ESD1  PESD3V3S2UT  [SOT-23]
J2  SWD  [SIP-5-2.54-6.0-R90]
J8  RST  [SIP-2-2.54]
J12  BOOT0  [SIP-2-2.54]
R10  RTT02103JTH,10K  [0402R]
R11  RTT02103JTH,10K  [0402R]
R12  RTT02103JTH,10K  [0402R]
R14  RTT02000JTH,0Ω  [0402R]
R17  2K,±1%  [0402R]
R18  RTT02103JTH,10K  [0402R]
R19  2K,±1%  [0402R]
R25  封装: 0402  [0402R]  (hidden comment: 0Ω,±5%)
R26  封装: 0402  [0402R]  (hidden comment: 0Ω,±5%)
R27  封装: 0402  [0402R]  (hidden comment: 0Ω,±5%)
R28  封装: 0402  [0402R]  (hidden comment: 0Ω,±5%)
R29  封装: 0402  [0402R]  (hidden comment: 0Ω,±5%)
R104  RTT02103JTH,10K  [0402R]
R105  RTT02103JTH,10K  [0402R]
S1  value 6×6×5.0mm,黑色  [KEY-6S]  (hidden comment: RST)
U2  ZLG237P48A  [QFP50P900X900X160-48L]
U5  ZLG217P64A  [QFP50P1200X1200X160-64L]
X1  JYD3A1C7G6-10-12.000,12.0000MHz  [OSCCC250X320X80-4N]
X2  SC-32S,32.768kHz  [XTAL320X150X90]

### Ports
3.3V_ZLG (in), GND, PA0/USART2_CTS (in), PA1/USART2_RTS (bidir), PA2/USART2_TX (in), PA3/USART2_RX (out), PA4/SPI1_NSS (in), PA5/SPI1_SCK (out), PA6/SPI1_MISO (out), PA7/SPI1_MOSI (in), PA8/PWM (bidir), PA9/UART1_TX (bidir), PA10/UART1_RX (bidir), PA15/PWM (bidir), PB0/ADC12_8 (out), PB1/ADC12_9 (in), PB2 (bidir), PB3/PWM (bidir), PB4/PWM (bidir), PB5/PWM (out), PB6/I2C1_SCL (in), PB7/I2C1_SDA (bidir), PB8/CANRX (in), PB9/CANTX (out), PB10/I2C2_SCL/UART3_TX (in), PB11/I2C2_SDA/UART3_RX (out), PB12/SPI2_NSS (in), PB13/SPI2_SCK (out), PB14/SPI2_MISO (in), PB15/SPI2_MOSI (out), PC0/ADC12_10 (in), PC1/ADC12_11 (out), PC2/ADC12_12 (out), PC3/ADC12_13 (in), PC4/ADC12_14 (out), PC5/ADC12_15 (bidir), PC6/PWM (in), PC7/PWM (bidir), PC8/PWM (in), PC9/PWM (out), PC10/UART3_TX (out), PC11/UART3_RX (out), PC12 (out), PC13 (bidir), PC14 (bidir), PC15 (bidir), PD2/PWM (bidir), RST (out), USB_N (bidir), USB_P (bidir)

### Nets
3.3V_ZLG: C7.1 C8.1 C10.1 C11.1 C12.1 D2.2 D3.1(D1) J2.1 J12.1 R10.2 R12.2 R14.1 R17.2 R19.2 R104.2 R105.2 U2.24(VDD) U2.36(VDD) U2.48(VDD) U5.19(DVDD) U5.32(DVDD) U5.48(DVDD) U5.64(DVDD) ; port 3.3V_ZLG  [project net 3.3V]
3.3VA_ZLG: C16.2 R14.2 U2.9(VDDA) U5.13(VDDA)
GND: BT1.2(-) C7.2 C8.2 C9.2 C10.2 C11.2 C12.2 C13.2 C14.2 C15.2 C16.1 C17.1 C18.2 C19.2 C20.2 C21.2 D4.1 D5.1 ESD1.3 J2.5 R11.1 R18.1 S1.1 S1.4 U2.8(VSSA) U2.23(VSS) U2.35(DVSS) U2.47(VSS) U5.12(VSSA) U5.18(DVSS) U5.31(DVSS) U5.47(DVSS) U5.63(DVSS) X1.2(GND) X1.4(GND) ; port GND
VBAT: C9.1 D3.3(A) U2.1(VBAT) U5.1(VBAT)
BOOT0: J12.2 R18.2 U2.44(BOOT0) U5.60(BOOT0)  [project net BOOT0_8]
NRST: C17.2 R25.2 U2.7(NRST) U5.7(NRST)  [project net NRST_8]
OSC_IN: C14.1 U2.5(PD0/OSC_IN) U5.5(PD0/OSC_IN) X1.1(X1)  [project net OSC_IN_8]
OSC_OUT: C15.1 U2.6(PD1/OSC_OUT) U5.6(PD1/OSC_OUT) X1.3(X2)  [project net OSC_OUT_8]
PA0/USART2_CTS: U2.10(PA0/ADC12_IN0/TIM2_CH1_ETR/USART2_CTS/WKUP) U5.14(PA0/ADC12_IN0/TIM2_CH1_ETR/USART2_CTS/WKUP) ; port PA0/USART2_CTS  [project net CTS/IO14_MicroP]
PA1/USART2_RTS: U2.11(PA1/ADC12_IN1/TIM2_CH2/USART2_RTS) U5.15(PA1/ADC12_IN1/TIM2_CH2/USART2_RTS) ; port PA1/USART2_RTS
PA2/USART2_TX: U2.12(PA2/ADC12_IN2/TIM2_CH3/USART2_TX) U5.16(PA2/ADC12_IN2/TIM2_CH3/USART2_TX) ; port PA2/USART2_TX  [project net UART2_TX]
PA3/USART2_RX: U2.13(PA3/ADC12_IN3/TIM2_CH4/USART2_RX) U5.17(PA3/ADC12_IN3/TIM2_CH4/USART2_RX) ; port PA3/USART2_RX  [project net UART2_RX]
PA4/SPI1_NSS: U2.14(PA4/ADC12_IN4/SPI1_NSS/USART2_CK) U5.20(PA4/ADC12_IN4/SPI1_NSS/USART2_CK) ; port PA4/SPI1_NSS  [project net SPI1_NSS]
PA5/SPI1_SCK: U2.15(PA5/ADC12_IN5/SPI1_SCK) U5.21(PA5/ADC12_IN5/SPI1_SCK) ; port PA5/SPI1_SCK  [project net SPI1_SCK]
PA6/SPI1_MISO: U2.16(PA6/ADC12_IN6/SPI1_MISO/TIM3_CH1/TIM1_BKIN) U5.22(PA6/ADC12_IN6/SPI1_MISO/TIM3_CH1/TIM1_BKIN) ; port PA6/SPI1_MISO  [project net SPI1_MISO]
PA7/SPI1_MOSI: U2.17(PA7/ADC12_IN7/SPI1_MOSI/TIM3_CH2/TIM1_CH1N) U5.23(PA7/ADC12_IN7/SPI1_MOSI/TIM3_CH2/TIM1_CH1N) ; port PA7/SPI1_MOSI  [project net SPI1_MOSI]
PA8/PWM: U2.29(PA8/TIM1_CH1/USART1_CK/MCO) U5.41(PA8/TIM1_CH1/USART1_CK/MCO) ; port PA8/PWM  [project net PA8]
PA9/UART1_TX: U2.30(PA9/TIM1_CH2/USART1_TX) U5.42(PA9/TIM1_CH2/USART1_TX) ; port PA9/UART1_TX  [project net UART1_TX]
PA10/UART1_RX: U2.31(PA10/TIM1_CH3/USART1_RX) U5.43(PA10/TIM1_CH3/USART1_RX) ; port PA10/UART1_RX  [project net UART1_RX]
PA15/PWM: U2.38(PA15/JTDI/TIM2_CH1_ETR/SPI1_NSS) U5.50(PA15/JTDI/TIM2_CH1_ETR/SPI1_NSS) ; port PA15/PWM  [project net PA15]
PB0/ADC12_8: U2.18(PB0/ADC12_IN8/TIM3_CH3/TIM1_CH2N) U5.26(PB0/ADC12_IN8/TIM3_CH3/TIM1_CH2N) ; port PB0/ADC12_8
PB1/ADC12_9: U2.19(PB1/ADC12_IN9/TIM3_CH4/TIM1_CH3N) U5.27(PB1/ADC12_IN9/TIM3_CH4/TIM1_CH3N) ; port PB1/ADC12_9
PB2: U2.20(PB2/BOOT1) U5.28(PB2/BOOT1) ; port PB2
PB3/PWM: U2.39(PB3/JTDO/TRACESWO/TIM2_CH2/SPI1_SCK) U5.55(PB3/JTDO/TRACESWO/TIM2_CH2/SPI1_SCK) ; port PB3/PWM  [project net PB3]
PB4/PWM: U2.40(PB4/NJTRST/TIM3_CH1/SPI1_MISO) U5.56(PB4/NJTRST/TIM3_CH1/SPI1_MISO) ; port PB4/PWM  [project net PB4]
PB5/PWM: U2.41(PB5/I2C1_SMBAI/TIM3_CH2/SPI1_MOSI) U5.57(PB5/I2C1_SMBAI/TIM3_CH2/SPI1_MOSI) ; port PB5/PWM  [project net PB5]
PB6: C20.1 D4.2 R17.1 R28.1 U2.42(PB6/I2C1_SCL/TIM4_CH1/USART1_TX) U5.58(PB6/I2C1_SCL/TIM4_CH1/USART1_TX)  [project net PB6_8]
PB6/I2C1_SCL: R28.2 ; port PB6/I2C1_SCL  [project net I2C1_SCL]
PB7: C21.1 D5.2 R19.1 R29.1 U2.43(PB7/I2C1_SDA/TIM4_CH2/USART1_RX) U5.59(PB7/I2C1_SDA/TIM4_CH2/USART1_RX)  [project net PB7_8]
PB7/I2C1_SDA: R29.2 ; port PB7/I2C1_SDA  [project net I2C1_SDA]
PB8/CANRX: U2.45(PB8/TIM4_CH3/I2C1_SCL/CANRX) U5.61(PB8/TIM4_CH3/I2C1_SCL/CANRX) ; port PB8/CANRX  [project net CAN0_RX_Aworks]
PB9/CANTX: U2.46(PB9/TIM4_CH4/I2C1_SDA/CANTX) U5.62(PB9/TIM4_CH4/I2C1_SDA/CANTX) ; port PB9/CANTX  [project net CAN0_TX_Aworks]
PB10/I2C2_SCL/UART3_TX: R104.1 U2.21(PB10/I2C2_SCL/USART3_TX/TIM2_CH3) U5.29(PB10/I2C2_SCL/USART3_TX/TIM2_CH3) ; port PB10/I2C2_SCL/UART3_TX
PB11/I2C2_SDA/UART3_RX: R105.1 U2.22(PB11/I2C2_SDA/USART3_RX/TIM2_CH4) U5.30(PB11/I2C2_SDA/USART3_RX/TIM2_CH4) ; port PB11/I2C2_SDA/UART3_RX
PB12/SPI2_NSS: U2.25(PB12/TIM1_BKIN/SPI2_NSS/USART2_CK/I2C2_SMBAI) U5.33(PB12/TIM1_BKIN/SPI2_NSS/USART2_CK/I2C2_SMBAI) ; port PB12/SPI2_NSS  [project net nCS0_Aworks]
PB13/SPI2_SCK: U2.26(PB13/TIM1_CH1N/SPI2_SCK/USART2_CTS) U5.34(PB13/TIM1_CH1N/SPI2_SCK/USART2_CTS) ; port PB13/SPI2_SCK
PB14/SPI2_MISO: U2.27(PB14/TIM1_CH2N/SPI2_MISO/USART2_RTS) U5.35(PB14/TIM1_CH2N/SPI2_MISO/USART2_RTS) ; port PB14/SPI2_MISO  [project net MISO_Aworks]
PB15/SPI2_MOSI: U2.28(PB15/TIM1_CH3N/SPI2_MOSI) U5.36(PB15/TIM1_CH3N/SPI2_MOSI) ; port PB15/SPI2_MOSI  [project net MOSI_Aworks]
PC0/ADC12_10: U5.8(PC0/ADC12_IN10) ; port PC0/ADC12_10
PC1/ADC12_11: U5.9(PC1/ADC12_IN11) ; port PC1/ADC12_11
PC2/ADC12_12: U5.10(PC2/ADC12_IN12) ; port PC2/ADC12_12
PC3/ADC12_13: U5.11(PC3/ADC12_IN13) ; port PC3/ADC12_13
PC4/ADC12_14: U5.24(PC4/ADC12_IN14) ; port PC4/ADC12_14
PC5/ADC12_15: U5.25(PC5/ADC12_IN15) ; port PC5/ADC12_15
PC6/PWM: U5.37(PC6/TIM3_CH1) ; port PC6/PWM
PC7/PWM: U5.38(PC7/TIM3_CH2) ; port PC7/PWM
PC8/PWM: U5.39(PC8/TIM3_CH3) ; port PC8/PWM
PC9/PWM: U5.40(PC9/TIM3_CH4) ; port PC9/PWM
PC10/UART3_TX: U5.51(PC10/USART3_TX) ; port PC10/UART3_TX
PC11/UART3_RX: U5.52(PC11/USART3_RX) ; port PC11/UART3_RX
PC12: U5.53(PC12/USART3_CK) ; port PC12
PC13: U2.2(PC13/TAMPER-RTC) U5.2(PC13/TAMPER-RTC) ; port PC13
PC14: R26.1 U2.3(PC14/OSC32_IN) U5.3(PC14/OSC32_IN) ; port PC14
PC15: R27.1 U2.4(PC15/OSC32_OUT) U5.4(PC15/OSC32_OUT) ; port PC15
PD2/PWM: U5.54(PD2/TIM3_ETR) ; port PD2/PWM
RST: J2.4 J8.1 R25.1 ; port RST
SWCLK/PA14: J2.3 R11.2 U2.37(PA14/JTCK/SWDCLK) U5.49(PA14/JTCK/SWDCLK)  [project net SWCLK/PA14_8]
SWDIO/PA13: J2.2 R10.1 U2.34(PA13/JTM/SWDIO) U5.46(PA13/JTM/SWDIO)  [project net SWDIO/PA13_8]
USB_N: U2.32(PA11/TIM1_CH4/USART1_CTS/USBDM/CANRX) U5.44(PA11/TIM1_CH4/USART1_CTS/USBDM/CANRX) ; port USB_N
USB_P: U2.33(PA12/TIM1_ETR/USART1_RTS/USBDP/CANTX) U5.45(PA12/TIM1_ETR/USART1_RTS/USBDP/CANTX) ; port USB_P
NetBT1_1: BT1.1(+) D3.2(D2)
NetC13_1: C13.1 D2.1 ESD1.1 ESD1.2 J8.2 R12.1 S1.2 S1.3
NetC18_1: C18.1 R26.2 X2.2
NetC19_1: C19.1 R27.2 X2.1

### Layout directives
differential pair: USB_N, USB_P

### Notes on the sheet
- 电源电容
- 靠近MCU电源端摆放
- 模拟电源
- VBAT电源
- SWD接口
- (near J2) 3.3V
  SWDIO
  SWCLK
  RST
  GND
- (near J2) 调试接口
- 复位
- RST
- 时钟
- 注意：蓝色网络名是64脚芯片网络
- (near R18) BOOT0配置
- (near J12) BOOT0
- 上拉电阻

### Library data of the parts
BT1 = 1.10.05.0281: 2P,间距1.25mm,Wafer凹槽边框,90°,WCON; 名称: 插座; 贴片和直插: SMT; PCB备注: 160927 hcj; 器件优选方案: 正常状态，可以选用
C7 = 1.02.02.0055: as C1 on sheet 02.power
C8-C12 C17 = 1.02.17.0006: as C5 on sheet 02.power
C13 = 1.02.17.0092: as C2 on sheet 02.power
C14 C15 = 1.02.17.0036: GRM1555C1H220JA01D,22pF,±5%,50V,C0G,0402,muRata,RoHS; 名称: 电容; 封装: 0402; 设备封装名称: C0402_22PF_NPO_50V_5%; 贴片和直插: SMT; 器件优选方案: 正常状态，可以选用
C16 = 1.02.01.0080: as C6 on sheet 01.Main
C18 C19 = 1.02.17.0008: GRM1555C1H100JA01D,10PF,±0.5PF,50V,COG,0402,muRata,RoHS; 名称: 电容; 贴片和直插: SMT; 器件优选方案: 正常状态，可以选用; 设备封装名称: C0402_10PF_COG_50V_+-0.5PF
C20 C21 = 1.02.17.0043: 5PF,±0.25%,50V,COG,GRM1555C1H5R0CA01D,0402,RoHS; 名称: 电容; 封装: 0402; 贴片和直插: SMT; 器件优选方案: 正常状态，可以选用
D2 = 1.04.07.0027: as D1 on sheet 03.板载外设
D3 = 1.04.07.0033: BAT54C,共阴,200mA,30V,SOT-23-3,NXP,RoHS; 名称: 二极管; 贴片和直插: SMT; 器件优选方案: 正常状态，可以选用
D4 D5 = 1.04.03.0050: PESD5V0S1UB,SOD-523,Nexperia; 名称: ESD静电保护器; 贴片和直插: SMT; PCB备注: 180419ZW; 器件优选方案: 正常状态，可以选用
ESD1 = 1.05.10.0361: PESD3V3S2UT,SOT-23,NXP,RoHS; 名称: 集成电路; 设备封装名称: SOT-23_PESD3V3S2UT; 贴片和直插: SMT; 器件优选方案: 量产物料,优先选用
J2 = CON5: Connector
J8 J12 = CON2: Connector
R10-R12 R18 R104 R105 = 1.01.17.0006: as R1 on sheet 03.板载外设
R14 = 1.01.17.0004: RTT02000JTH,0Ω,±5%,0402,RALEC,RoHS; 名称: 电阻; 封装: 0402; 设备封装名称: R0402_0R; 贴片和直插: SMT; 器件优选方案: 正常状态，可以选用
R17 R19 = 1.01.17.0064: 2K,±1%,1/16W,0402,RoHS; 名称: 电阻; 封装: 0402; 设备封装名称: R0402_2K_1%; 厂商: Ralec; 贴片和直插: SMT; 器件优选方案: 正常状态，可以选用
R25-R29 = 1.01.17.0004: as R9 on sheet 01.Main
S1 = 1.09.01.0003: as S2 on sheet 03.板载外设
U5 = 1.05.02.0207: ZLG217P64A,LQFP64,ZLG; 名称: 集成电路; 贴片和直插: SMT; PCB备注: 171017lmd; 器件优选方案: 正常状态，可以选用
X1 = 1.07.01.0032: JYD3A1C7G6-10-12.000,12.0000MHz,±10ppm,10pF,-40~85℃,±10ppm,SMD3225,*,JYEG,RoHS; 名称: 晶体; 贴片和直插: SMT; PCB备注: 151229lmd171128ZW; 器件优选方案: 正常状态，可以选用
X2 = 1.07.02.0056: SC-32S,32.768kHz,12.5pF,±20ppm,SMD3215,SII,RoHS,金属; 名称: 晶体; 贴片和直插: SMT; 器件优选方案: 正常状态，可以选用

## Sheet 07.USB Device_MicroUSB_CON.SchDoc
size A4; productModel: Easy-ZMF159; productName: 开发套件; CheckedBy: <审核日期>; Author: <设计人员>; CompanyName: 广州立功科技股份有限; DocumentNumber: 7; SheetNumber: 7; SheetTotal: 8; PageSetup: Record=PageOptions|CenterHorizontal=True|CenterVertical=True|PrintScale=1.00|XCorrection=1.00|YCorrection=1.00|PrintKind=0|BorderSize=5000000|LeftOffset=0|BottomOffset=0|Orientation=2|PaperLength=1000|PaperWidth=1000|Scale=100|PaperSource=7|PrintQuality=600|MediaType=1|DitherType=10|PaperKind=A4|PrintScaleMode=1; DesignDate: <设计日期>; CheckDate: <审核人员>; SheetName: <图纸名称>; SheetVersion: <图纸版本>; SheetDescription: <图纸描述>
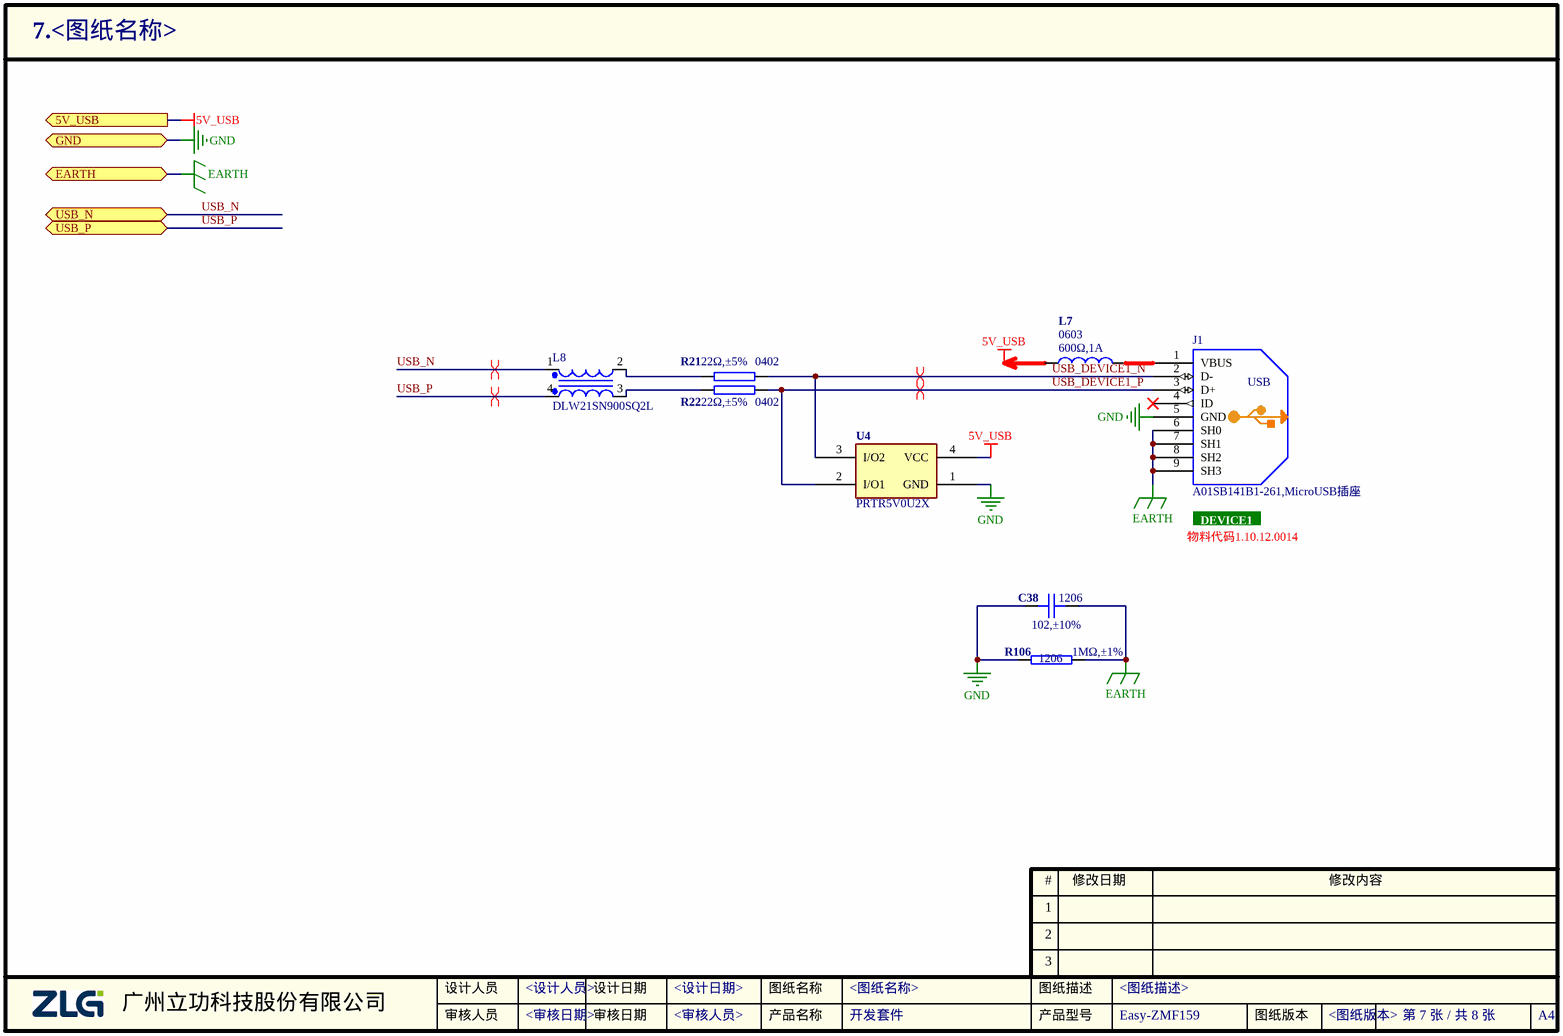
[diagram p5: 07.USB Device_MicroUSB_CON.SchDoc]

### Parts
C38  封装: 1206  [1206C]  (hidden comment: 102,±10%)
J1  A01SB141B1-261,MicroUSB插座  [MICROUSB-5S]
L7  封装: 0603  [0603L]  (hidden comment: 600Ω,1A)
L8  DLW21SN900SQ2L  [FIL_DLW21S]
R21  封装: 0402  [0402R]  (hidden comment: 22Ω,±5%)
R22  封装: 0402  [0402R]  (hidden comment: 22Ω,±5%)
R106  封装: 1206  [1206R]  (hidden comment: 1MΩ,±1%)
U4  PRTR5V0U2X  [SOT-143]

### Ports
5V_USB (out), EARTH, GND, USB_N (bidir), USB_P (bidir)

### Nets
5V_USB: L7.1 U4.4(VCC) ; port 5V_USB  [project net 5V]
EARTH: C38.2 J1.6(SH0) J1.7(SH1) J1.8(SH2) J1.9(SH3) R106.2 ; port EARTH
GND: C38.1 J1.5(GND) R106.1 U4.1(GND) ; port GND
USB_DEVICE1_N: J1.2(D-) R21.2 U4.3(I/O2)  [project net USB_DEVICE1_N_7]
USB_DEVICE1_P: J1.3(D+) R22.1 U4.2(I/O1)  [project net USB_DEVICE1_P_7]
USB_N: L8.1 ; port USB_N
USB_P: L8.4 ; port USB_P
NetJ1_1: J1.1(VBUS) L7.2
NetL8_2: L8.2 R21.1
NetL8_3: L8.3 R22.2

Not connected (* = marked no-connect by the designer): J1 4(ID)*

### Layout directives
differential pair: USB_DEVICE1_N_7, USB_DEVICE1_P_7, USB_N, USB_P

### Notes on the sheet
- (near J1) DEVICE1
- 物料代码1.10.12.0014

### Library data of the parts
C38 = 1.02.03.0003: 102,±10%,2KV,X7R,1206,*,RoHS; 名称: 电容; 设备封装名称: C1206_102_X7R_2KV_10%; 贴片和直插: SMT
J1 = 1.10.12.0014: A01SB141B1-261,MicroUSB插座,SMT,艾立信,RoHS; PCB备注: 141030lmd; 器件优选方案: 正常状态，可以选用
L7 = 1.03.03.0012: 600Ω,1A,DCR200mΩ,BH03Y314S-600R,SMD,0603,丰晶,RoHS; 名称: 磁珠; 贴片和直插: SMT; 器件优选方案: 正常状态，可以选用
L8 = 1.03.01.0113: DLW21SN900SQ2L,SLN4-0805,村田,RoHS; 名称: 电感; 厂商: Murata; 贴片和直插: SMT; PCB备注: 181221ZW; 器件优选方案: 正常状态，可以选用
R21 R22 = 1.01.17.0023: 22Ω,±5%,0402,RALEC,RoHS; 名称: 电阻; 设备封装名称: R0402_22R; 贴片和直插: SMT; 器件优选方案: 正常状态，可以选用
R106 = 1.01.03.0024: 1MΩ,±1%,1206,RoHS; 名称: 电阻; 设备封装名称: R1206_1M_1%; 贴片和直插: SMT
U4 = 1.05.10.0153: PRTR5V0U2X,SOT-143B,NXP,RoHS; 名称: 集成电路; 设备封装名称: SOT-143B_PRTR5V0U2X; 贴片和直插: SMT; 器件优选方案: 量产物料,优先选用

## Sheet 04.Microport.SchDoc
size A4; productModel: Easy-ZMF159; productName: 开发套件; CheckedBy: <审核日期>; Author: <设计人员>; CompanyName: 广州立功科技股份有限; DocumentNumber: 4; SheetNumber: 4; SheetTotal: 8; PageSetup: Record=PageOptions|CenterHorizontal=True|CenterVertical=True|PrintScale=1.00|XCorrection=1.00|YCorrection=1.00|PrintKind=0|BorderSize=5000000|LeftOffset=0|BottomOffset=0|Orientation=2|PaperLength=1000|PaperWidth=1000|Scale=100|PaperSource=7|PrintQuality=600|MediaType=1|DitherType=10|PaperKind=A4|PrintScaleMode=1; DesignDate: <设计日期>; CheckDate: <审核人员>; SheetName: <图纸名称>; SheetVersion: <图纸版本>; SheetDescription: <图纸描述>
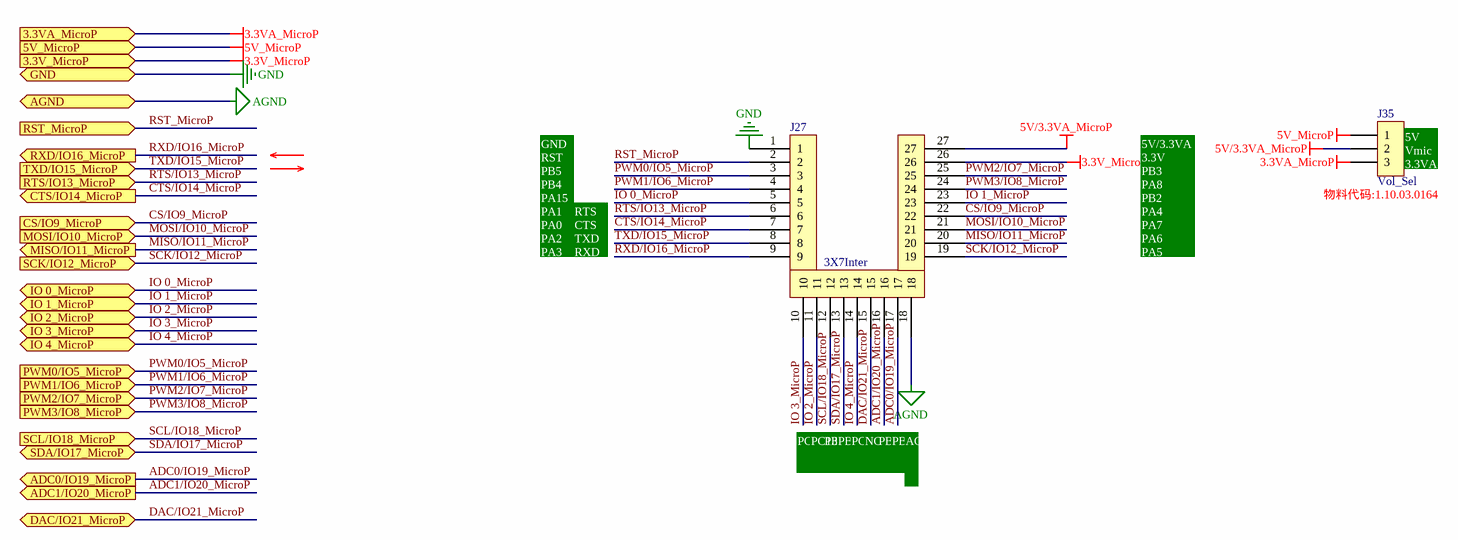
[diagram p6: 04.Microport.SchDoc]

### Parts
J27  3X7Inter  [SIP-27 2.54C]
J35  Vol_Sel  [SIP-3-2.54]

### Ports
3.3V_MicroP (in), 3.3VA_MicroP (in), 5V_MicroP (in), ADC0/IO19_MicroP (out), ADC1/IO20_MicroP (out), AGND, CS/IO9_MicroP (in), CTS/IO14_MicroP (out), DAC/IO21_MicroP (bidir), GND, IO 0_MicroP (bidir), IO 1_MicroP (bidir), IO 2_MicroP (bidir), IO 3_MicroP (bidir), IO 4_MicroP (bidir), MISO/IO11_MicroP (out), MOSI/IO10_MicroP (in), PWM0/IO5_MicroP (in), PWM1/IO6_MicroP (in), PWM2/IO7_MicroP (in), PWM3/IO8_MicroP (in), RST_MicroP (in), RTS/IO13_MicroP (in), RXD/IO16_MicroP (out), SCK/IO12_MicroP (in), SCL/IO18_MicroP (in), SDA/IO17_MicroP (bidir), TXD/IO15_MicroP (in)

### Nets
3.3V_MicroP: J27.26 ; port 3.3V_MicroP  [project net 3.3V]
3.3VA_MicroP: J35.3 ; port 3.3VA_MicroP  [project net 3.3VA]
5V/3.3VA_MicroP: J27.27 J35.2
5V_MicroP: J35.1 ; port 5V_MicroP  [project net 5V]
AGND: J27.18 ; port AGND
GND: J27.1 ; port GND
ADC0/IO19_MicroP: J27.17 ; port ADC0/IO19_MicroP  [project net PB0/ADC12_8]
ADC1/IO20_MicroP: J27.16 ; port ADC1/IO20_MicroP  [project net PB1/ADC12_9]
CS/IO9_MicroP: J27.22 ; port CS/IO9_MicroP  [project net SPI1_NSS]
CTS/IO14_MicroP: J27.7 ; port CTS/IO14_MicroP
DAC/IO21_MicroP: J27.15 ; port DAC/IO21_MicroP
IO 0_MicroP: J27.5 ; port IO 0_MicroP  [project net PA15]
IO 1_MicroP: J27.23 ; port IO 1_MicroP  [project net PB2]
IO 2_MicroP: J27.11 ; port IO 2_MicroP  [project net PC13]
IO 3_MicroP: J27.10 ; port IO 3_MicroP  [project net PC14]
IO 4_MicroP: J27.14 ; port IO 4_MicroP  [project net PC15]
MISO/IO11_MicroP: J27.20 ; port MISO/IO11_MicroP  [project net SPI1_MISO]
MOSI/IO10_MicroP: J27.21 ; port MOSI/IO10_MicroP  [project net SPI1_MOSI]
PWM0/IO5_MicroP: J27.3 ; port PWM0/IO5_MicroP  [project net PB5]
PWM1/IO6_MicroP: J27.4 ; port PWM1/IO6_MicroP  [project net PB4]
PWM2/IO7_MicroP: J27.25 ; port PWM2/IO7_MicroP  [project net PB3]
PWM3/IO8_MicroP: J27.24 ; port PWM3/IO8_MicroP  [project net PA8]
RST_MicroP: J27.2 ; port RST_MicroP  [project net RST]
RTS/IO13_MicroP: J27.6 ; port RTS/IO13_MicroP  [project net PA1/USART2_RTS]
RXD/IO16_MicroP: J27.9 ; port RXD/IO16_MicroP  [project net UART2_RX]
SCK/IO12_MicroP: J27.19 ; port SCK/IO12_MicroP  [project net SPI1_SCK]
SCL/IO18_MicroP: J27.12 ; port SCL/IO18_MicroP  [project net I2C1_SCL]
SDA/IO17_MicroP: J27.13 ; port SDA/IO17_MicroP  [project net I2C1_SDA]
TXD/IO15_MicroP: J27.8 ; port TXD/IO15_MicroP  [project net UART2_TX]

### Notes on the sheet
- (near J35) 5V
- (near J35) 物料代码:1.10.03.0164
- (near J35) Vmic
  3.3VA
- GND
  RST
  PB5
  PB4
  PA15
  PA1
  PA0
  PA2
  PA3
- TXD
- RXD
- RTS
- CTS
- 5V/3.3VA
  3.3V
  PB3
  PA8
  PB2
  PA4
  PA7
  PA6
  PA5
- PC14
- PC13
- PB6
- PB7
- PC15
- NC
- PB1
- PB0
- AGND

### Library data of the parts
J27 = 3X7Inter: 物料代码: 1.10.11.0074
J35 = CON3: Connector; 物料代码: 1.10.03.0164

## Sheet 05.Miniport.SchDoc
size A4; productModel: Easy-ZLG237; productName: 开发套件; CheckedBy: <审核日期>; Author: <设计人员>; CompanyName: 广州立功科技股份有限; DocumentNumber: 5; SheetNumber: 5; SheetTotal: 8; PageSetup: Record=PageOptions|CenterHorizontal=True|CenterVertical=True|PrintScale=1.00|XCorrection=1.00|YCorrection=1.00|PrintKind=0|BorderSize=5000000|LeftOffset=0|BottomOffset=0|Orientation=2|PaperLength=1000|PaperWidth=1000|Scale=100|PaperSource=7|PrintQuality=600|MediaType=1|DitherType=10|PaperKind=A4|PrintScaleMode=1; DesignDate: <设计日期>; CheckDate: <审核人员>; SheetName: <图纸名称>; SheetVersion: <图纸版本>; SheetDescription: <图纸描述>
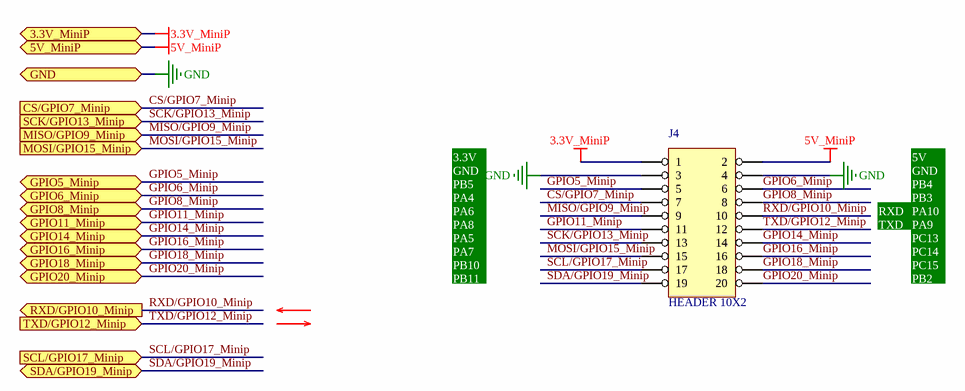
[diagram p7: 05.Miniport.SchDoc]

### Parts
J4  HEADER 10X2  [IDC-20-2.54-R90]

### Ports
3.3V_MiniP, 5V_MiniP, CS/GPIO7_Minip (in), GND, GPIO5_Minip (bidir), GPIO6_Minip (bidir), GPIO8_Minip (bidir), GPIO11_Minip (bidir), GPIO14_Minip (bidir), GPIO16_Minip (bidir), GPIO18_Minip (bidir), GPIO20_Minip (bidir), MISO/GPIO9_Minip (in), MOSI/GPIO15_Minip (in), RXD/GPIO10_Minip (out), SCK/GPIO13_Minip (in), SCL/GPIO17_Minip (in), SDA/GPIO19_Minip (bidir), TXD/GPIO12_Minip (in)

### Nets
3.3V_MiniP: J4.1 ; port 3.3V_MiniP  [project net 3.3V]
5V_MiniP: J4.2 ; port 5V_MiniP  [project net 5V]
GND: J4.3 J4.4 ; port GND
CS/GPIO7_Minip: J4.7 ; port CS/GPIO7_Minip  [project net SPI1_NSS]
GPIO5_Minip: J4.5 ; port GPIO5_Minip  [project net PB5]
GPIO6_Minip: J4.6 ; port GPIO6_Minip  [project net PB4]
GPIO8_Minip: J4.8 ; port GPIO8_Minip  [project net PB3]
GPIO11_Minip: J4.11 ; port GPIO11_Minip  [project net PA8]
GPIO14_Minip: J4.14 ; port GPIO14_Minip  [project net PC13]
GPIO16_Minip: J4.16 ; port GPIO16_Minip  [project net PC14]
GPIO18_Minip: J4.18 ; port GPIO18_Minip  [project net PC15]
GPIO20_Minip: J4.20 ; port GPIO20_Minip  [project net PB2]
MISO/GPIO9_Minip: J4.9 ; port MISO/GPIO9_Minip  [project net SPI1_MISO]
MOSI/GPIO15_Minip: J4.15 ; port MOSI/GPIO15_Minip  [project net SPI1_MOSI]
RXD/GPIO10_Minip: J4.10 ; port RXD/GPIO10_Minip  [project net UART1_RX]
SCK/GPIO13_Minip: J4.13 ; port SCK/GPIO13_Minip  [project net SPI1_SCK]
SCL/GPIO17_Minip: J4.17 ; port SCL/GPIO17_Minip  [project net I2C2_SCL]
SDA/GPIO19_Minip: J4.19 ; port SDA/GPIO19_Minip  [project net I2C2_SDA]
TXD/GPIO12_Minip: J4.12 ; port TXD/GPIO12_Minip  [project net UART1_TX]

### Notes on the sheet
- 3.3V
  GND
  PB5
  PA4
  PA6
  PA8
  PA5
  PA7
  PB10
  PB11
- TXD
- RXD
- 5V
  GND
  PB4
  PB3
  PA10
  PA9
  PC13
  PC14
  PC15
  PB2

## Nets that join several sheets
3.3V: 01.Main (R13.1), 02.power (LED2.1 R16.2 T3.1), 03.板载外设 (9 pins), 06.AworksPort_MCU (J32.24), 08.ZLG237 (23 pins), 04.Microport (J27.26), 05.Miniport (J4.1)
3.3VA: 01.Main (C6.1 R13.2), 06.AworksPort_MCU (J31.23), 04.Microport (J35.3)
5V: 02.power (5 pins), 03.板载外设 (R7.1), 06.AworksPort_MCU (J31.25 J32.26), 07.USB Device_MicroUSB_CON (L7.1 U4.4), 04.Microport (J35.1), 05.Miniport (J4.2)
AGND: 01.Main (C6.2 L2.2), 03.板载外设 (C37.2 R97.2), 06.AworksPort_MCU (J31.21), 04.Microport (J27.18)
EARTH: 01.Main (HOLE1.1), 07.USB Device_MicroUSB_CON (6 pins)
GND: 01.Main (L2.1), 02.power (8 pins), 03.板载外设 (8 pins), 06.AworksPort_MCU (J31.26 J32.23 J32.25), 08.ZLG237 (35 pins), 07.USB Device_MicroUSB_CON (C38.1 J1.5 R106.1 U4.1), 04.Microport (J27.1), 05.Miniport (J4.3 J4.4)
CAN0_RX_Aworks: 06.AworksPort_MCU (J32.9), 08.ZLG237 (U2.45 U5.61)
CAN0_TX_Aworks: 06.AworksPort_MCU (J32.10), 08.ZLG237 (U2.46 U5.62)
CTS/IO14_MicroP: 08.ZLG237 (U2.10 U5.14), 04.Microport (J27.7)
I2C1_SCL: 03.板载外设 (J11.1), 06.AworksPort_MCU (J31.16), 08.ZLG237 (R28.2), 04.Microport (J27.12)
I2C1_SDA: 03.板载外设 (J13.1), 06.AworksPort_MCU (J31.15), 08.ZLG237 (R29.2), 04.Microport (J27.13)
I2C2_SCL: 01.Main (R9.2), 05.Miniport (J4.17)
I2C2_SDA: 01.Main (R23.2), 05.Miniport (J4.19)
MISO_Aworks: 06.AworksPort_MCU (J32.3), 08.ZLG237 (U2.27 U5.35)
MOSI_Aworks: 06.AworksPort_MCU (J32.4), 08.ZLG237 (U2.28 U5.36)
nCS0_Aworks: 06.AworksPort_MCU (J32.2), 08.ZLG237 (U2.25 U5.33)
PA1/USART2_RTS: 08.ZLG237 (U2.11 U5.15), 04.Microport (J27.6)
PA8: 06.AworksPort_MCU (J31.13), 08.ZLG237 (U2.29 U5.41), 04.Microport (J27.24), 05.Miniport (J4.11)
PA15: 03.板载外设 (J7.1), 06.AworksPort_MCU (J31.1), 08.ZLG237 (U2.38 U5.50), 04.Microport (J27.5)
PB0/ADC12_8: 03.板载外设 (J6.1), 08.ZLG237 (U2.18 U5.26), 04.Microport (J27.17)
PB1/ADC12_9: 08.ZLG237 (U2.19 U5.27), 04.Microport (J27.16)
PB2: 03.板载外设 (J14.1 R8.2), 08.ZLG237 (U2.20 U5.28), 04.Microport (J27.23), 05.Miniport (J4.20)
PB3: 03.板载外设 (J10.1), 06.AworksPort_MCU (J31.14), 08.ZLG237 (U2.39 U5.55), 04.Microport (J27.25), 05.Miniport (J4.8)
PB4: 06.AworksPort_MCU (J32.5), 08.ZLG237 (U2.40 U5.56), 04.Microport (J27.4), 05.Miniport (J4.6)
PB5: 06.AworksPort_MCU (J32.6), 08.ZLG237 (U2.41 U5.57), 04.Microport (J27.3), 05.Miniport (J4.5)
PB10/I2C2_SCL/UART3_TX: 01.Main (R9.1 R20.1), 08.ZLG237 (R104.1 U2.21 U5.29)
PB11/I2C2_SDA/UART3_RX: 01.Main (R23.1 R24.1), 08.ZLG237 (R105.1 U2.22 U5.30)
PB13/SPI2_SCK: 06.AworksPort_MCU (J32.1), 08.ZLG237 (U2.26 U5.34)
PC0/ADC12_10: 06.AworksPort_MCU (J31.20), 08.ZLG237 (U5.8)
PC1/ADC12_11: 06.AworksPort_MCU (J31.19), 08.ZLG237 (U5.9)
PC2/ADC12_12: 06.AworksPort_MCU (J31.18), 08.ZLG237 (U5.10)
PC3/ADC12_13: 06.AworksPort_MCU (J31.17), 08.ZLG237 (U5.11)
PC4/ADC12_14: 06.AworksPort_MCU (J31.7), 08.ZLG237 (U5.24)
PC5/ADC12_15: 06.AworksPort_MCU (J31.8), 08.ZLG237 (U5.25)
PC6/PWM: 06.AworksPort_MCU (J31.4), 08.ZLG237 (U5.37)
PC7/PWM: 06.AworksPort_MCU (J31.6), 08.ZLG237 (U5.38)
PC8/PWM: 06.AworksPort_MCU (J31.5), 08.ZLG237 (U5.39)
PC9/PWM: 06.AworksPort_MCU (J31.3), 08.ZLG237 (U5.40)
PC10/UART3_TX: 06.AworksPort_MCU (J32.16), 08.ZLG237 (U5.51)
PC11/UART3_RX: 06.AworksPort_MCU (J32.15), 08.ZLG237 (U5.52)
PC12: 06.AworksPort_MCU (J31.9), 08.ZLG237 (U5.53)
PC13: 03.板载外设 (J9.1), 06.AworksPort_MCU (J31.12), 08.ZLG237 (U2.2 U5.2), 04.Microport (J27.11), 05.Miniport (J4.14)
PC14: 06.AworksPort_MCU (J31.11), 08.ZLG237 (R26.1 U2.3 U5.3), 04.Microport (J27.10), 05.Miniport (J4.16)
PC15: 06.AworksPort_MCU (J31.10), 08.ZLG237 (R27.1 U2.4 U5.4), 04.Microport (J27.14), 05.Miniport (J4.18)
PD2/PWM: 06.AworksPort_MCU (J31.2), 08.ZLG237 (U5.54)
RST: 08.ZLG237 (J2.4 J8.1 R25.1), 04.Microport (J27.2)
SPI1_MISO: 08.ZLG237 (U2.16 U5.22), 04.Microport (J27.20), 05.Miniport (J4.9)
SPI1_MOSI: 08.ZLG237 (U2.17 U5.23), 04.Microport (J27.21), 05.Miniport (J4.15)
SPI1_NSS: 08.ZLG237 (U2.14 U5.20), 04.Microport (J27.22), 05.Miniport (J4.7)
SPI1_SCK: 08.ZLG237 (U2.15 U5.21), 04.Microport (J27.19), 05.Miniport (J4.13)
UART1_RX: 06.AworksPort_MCU (J32.21), 08.ZLG237 (U2.31 U5.43), 05.Miniport (J4.10)
UART1_TX: 06.AworksPort_MCU (J32.22), 08.ZLG237 (U2.30 U5.42), 05.Miniport (J4.12)
UART2_RX: 06.AworksPort_MCU (J32.19), 08.ZLG237 (U2.13 U5.17), 04.Microport (J27.9)
UART2_TX: 06.AworksPort_MCU (J32.20), 08.ZLG237 (U2.12 U5.16), 04.Microport (J27.8)
UART3_RX: 01.Main (R24.2), 06.AworksPort_MCU (J32.17)
UART3_TX: 01.Main (R20.2), 06.AworksPort_MCU (J32.18)
USB_N: 08.ZLG237 (U2.32 U5.44), 07.USB Device_MicroUSB_CON (L8.1)
USB_P: 08.ZLG237 (U2.33 U5.45), 07.USB Device_MicroUSB_CON (L8.4)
